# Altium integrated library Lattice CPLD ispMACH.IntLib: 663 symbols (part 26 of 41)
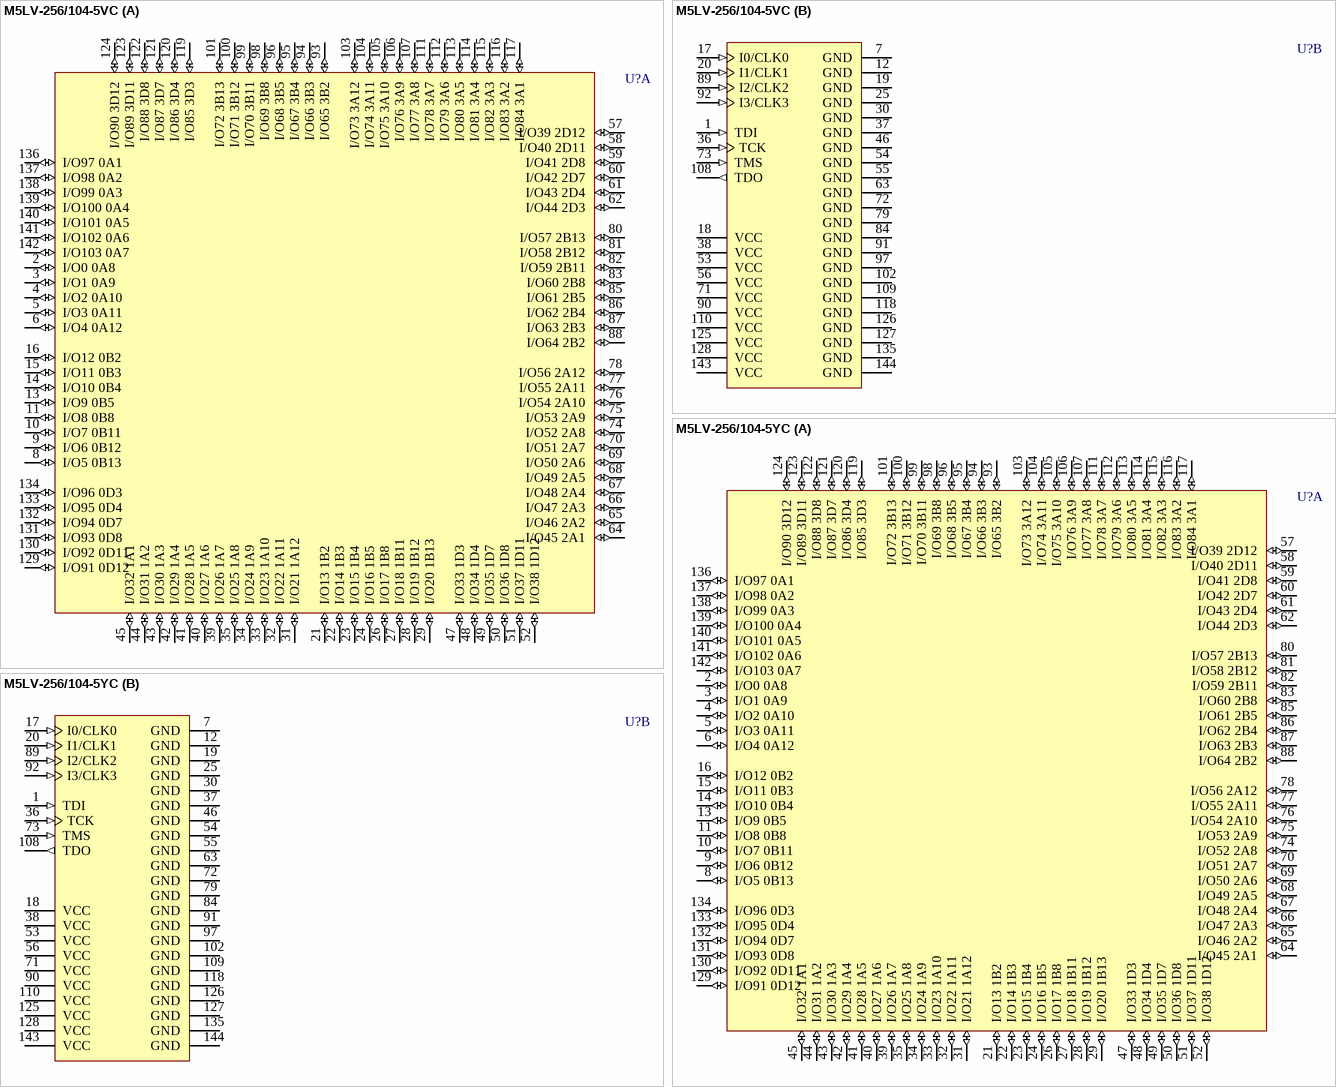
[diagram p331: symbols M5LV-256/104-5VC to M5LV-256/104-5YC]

## M5LV-256/104-5YC
designator U?
High-Density and High-I/O Complex PLD
footprint PQFP144_N (QFP, 144-Leads, Body 28 x 28mm, Pitch 0.65mm, IPC Medium Density)
footprint PQFP144_L (QFP, 144-Leads, Body 28 x 28mm, Pitch 0.65mm, IPC High Density)
footprint PQFP144_M (QFP, 144-Leads, Body 28 x 28mm, Pitch 0.65mm, IPC Low Density)
3D model M5LV-PQFP144 (144-Pin Quad Flat Pack 0.65 mm Pitch)
part A pins: 2 I/O0 0A8 (io), 3 I/O1 0A9 (io), 4 I/O2 0A10 (io), 5 I/O3 0A11 (io), 6 I/O4 0A12 (io), 8 I/O5 0B13 (io), 9 I/O6 0B12 (io), 10 I/O7 0B11 (io), 11 I/O8 0B8 (io), 13 I/O9 0B5 (io), 14 I/O10 0B4 (io), 15 I/O11 0B3 (io), 16 I/O12 0B2 (io), 21 I/O13 1B2 (io), 22 I/O14 1B3 (io), 23 I/O15 1B4 (io), 24 I/O16 1B5 (io), 26 I/O17 1B8 (io), 27 I/O18 1B11 (io), 28 I/O19 1B12 (io), 29 I/O20 1B13 (io), 31 I/O21 1A12 (io), 32 I/O22 1A11 (io), 33 I/O23 1A10 (io), 34 I/O24 1A9 (io), 35 I/O25 1A8 (io), 39 I/O26 1A7 (io), 40 I/O27 1A6 (io), 41 I/O28 1A5 (io), 42 I/O29 1A4 (io), 43 I/O30 1A3 (io), 44 I/O31 1A2 (io), 45 I/O32 1A1 (io), 47 I/O33 1D3 (io), 48 I/O34 1D4 (io), 49 I/O35 1D7 (io), 50 I/O36 1D8 (io), 51 I/O37 1D11 (io), 52 I/O38 1D12 (io), 57 I/O39 2D12 (io), 58 I/O40 2D11 (io), 59 I/O41 2D8 (io), 60 I/O42 2D7 (io), 61 I/O43 2D4 (io), 62 I/O44 2D3 (io), 64 I/O45 2A1 (io), 65 I/O46 2A2 (io), 66 I/O47 2A3 (io), 67 I/O48 2A4 (io), 68 I/O49 2A5 (io), 69 I/O50 2A6 (io), 70 I/O51 2A7 (io), 74 I/O52 2A8 (io), 75 I/O53 2A9 (io), 76 I/O54 2A10 (io), 77 I/O55 2A11 (io), 78 I/O56 2A12 (io), 80 I/O57 2B13 (io), 81 I/O58 2B12 (io), 82 I/O59 2B11 (io), 83 I/O60 2B8 (io), 85 I/O61 2B5 (io), 86 I/O62 2B4 (io), 87 I/O63 2B3 (io), 88 I/O64 2B2 (io), 93 I/O65 3B2 (io), 94 I/O66 3B3 (io), 95 I/O67 3B4 (io), 96 I/O68 3B5 (io), 98 I/O69 3B8 (io), 99 I/O70 3B11 (io), 100 I/O71 3B12 (io), 101 I/O72 3B13 (io), 103 I/O73 3A12 (io), 104 I/O74 3A11 (io), 105 I/O75 3A10 (io), 106 I/O76 3A9 (io), 107 I/O77 3A8 (io), 111 I/O78 3A7 (io), 112 I/O79 3A6 (io), 113 I/O80 3A5 (io), 114 I/O81 3A4 (io), 115 I/O82 3A3 (io), 116 I/O83 3A2 (io), 117 I/O84 3A1 (io), 119 I/O85 3D3 (io), 120 I/O86 3D4 (io), 121 I/O87 3D7 (io), 122 I/O88 3D8 (io), 123 I/O89 3D11 (io), 124 I/O90 3D12 (io), 129 I/O91 0D12 (io), 130 I/O92 0D11 (io), 131 I/O93 0D8 (io), 132 I/O94 0D7 (io), 133 I/O95 0D4 (io), 134 I/O96 0D3 (io), 136 I/O97 0A1 (io), 137 I/O98 0A2 (io), 138 I/O99 0A3 (io), 139 I/O100 0A4 (io), 140 I/O101 0A5 (io), 141 I/O102 0A6 (io), 142 I/O103 0A7 (io)
part B pins: 1 TDI (in), 7 GND (power), 12 GND (power), 17 I0/CLK0 (in), 18 VCC (power), 19 GND (power), 20 I1/CLK1 (in), 25 GND (power), 30 GND (power), 36 TCK (in), 37 GND (power), 38 VCC (power), 46 GND (power), 53 VCC (power), 54 GND (power), 55 GND (power), 56 VCC (power), 63 GND (power), 71 VCC (power), 72 GND (power), 73 TMS (in), 79 GND (power), 84 GND (power), 89 I2/CLK2 (in), 90 VCC (power), 91 GND (power), 92 I3/CLK3 (in), 97 GND (power), 102 GND (power), 108 TDO (out), 109 GND (power), 110 VCC (power), 118 GND (power), 125 VCC (power), 126 GND (power), 127 GND (power), 128 VCC (power), 135 GND (power), 143 VCC (power), 144 GND (power)

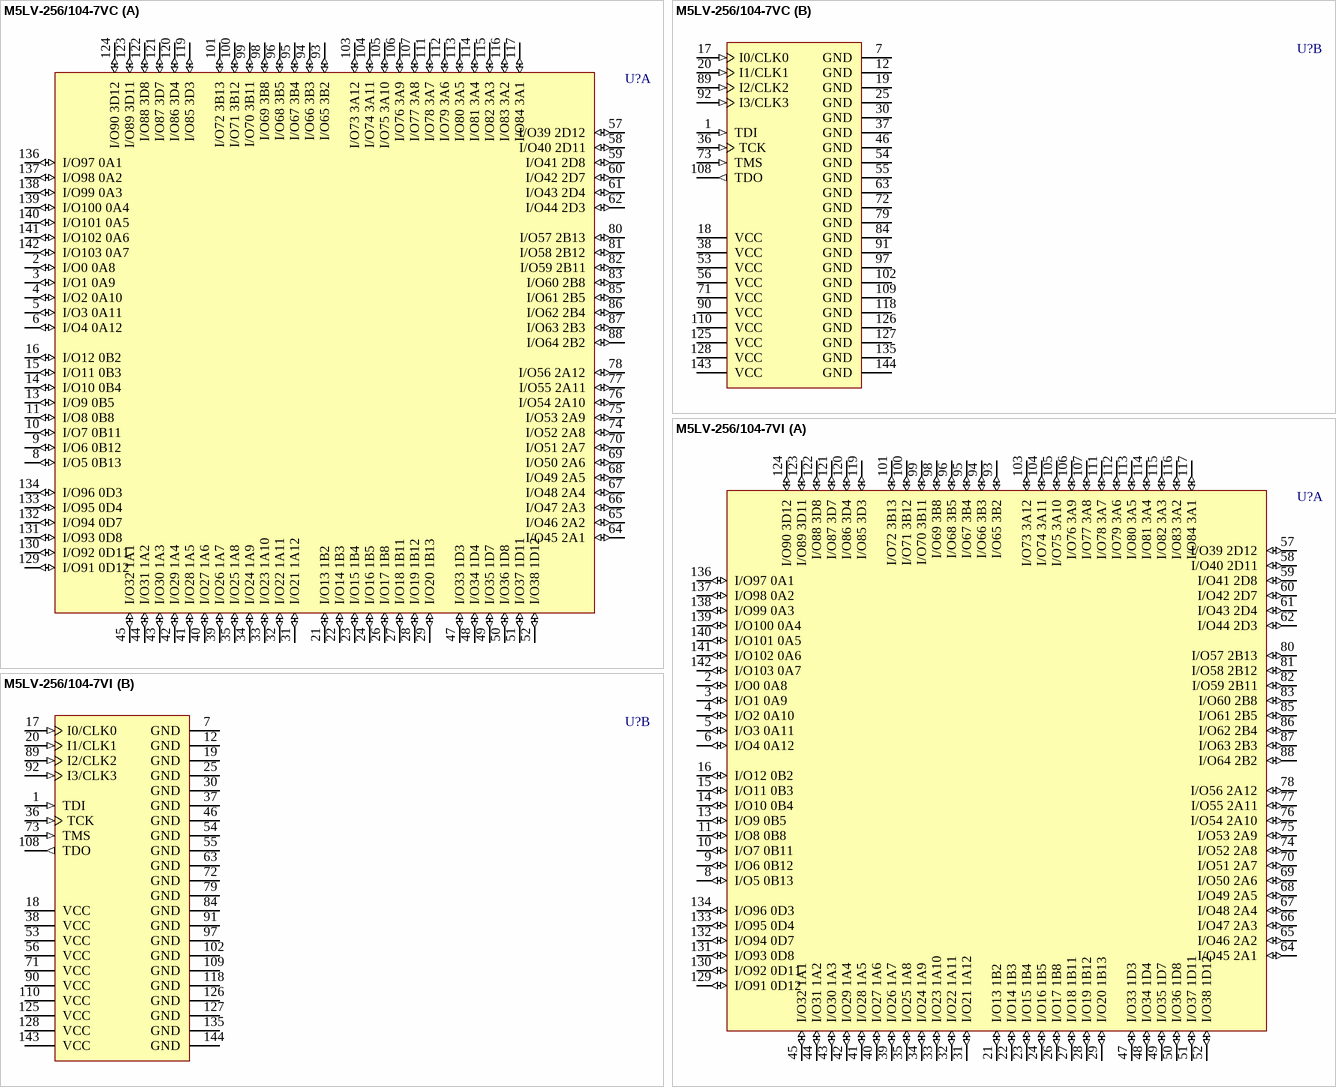
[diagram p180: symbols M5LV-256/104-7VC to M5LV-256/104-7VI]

## M5LV-256/104-7VC
designator U?
High-Density and High-I/O Complex PLD
footprint TQFP144_N (Thin QFP, 144-Leads, Body 20x20mm, Pitch 0.5mm, IPC Medium Density)
footprint TQFP144_L (Thin QFP, 144-Leads, Body 20x20mm, Pitch 0.5mm, IPC High Density)
footprint TQFP144_M (Thin QFP, 144-Leads, Body 20x20mm, Pitch 0.5mm, IPC Low Density)
3D model M5LV-TQFP144 (144-Pin Thin Quad Flat Pack (TQFP144))
part A pins: 2 I/O0 0A8 (io), 3 I/O1 0A9 (io), 4 I/O2 0A10 (io), 5 I/O3 0A11 (io), 6 I/O4 0A12 (io), 8 I/O5 0B13 (io), 9 I/O6 0B12 (io), 10 I/O7 0B11 (io), 11 I/O8 0B8 (io), 13 I/O9 0B5 (io), 14 I/O10 0B4 (io), 15 I/O11 0B3 (io), 16 I/O12 0B2 (io), 21 I/O13 1B2 (io), 22 I/O14 1B3 (io), 23 I/O15 1B4 (io), 24 I/O16 1B5 (io), 26 I/O17 1B8 (io), 27 I/O18 1B11 (io), 28 I/O19 1B12 (io), 29 I/O20 1B13 (io), 31 I/O21 1A12 (io), 32 I/O22 1A11 (io), 33 I/O23 1A10 (io), 34 I/O24 1A9 (io), 35 I/O25 1A8 (io), 39 I/O26 1A7 (io), 40 I/O27 1A6 (io), 41 I/O28 1A5 (io), 42 I/O29 1A4 (io), 43 I/O30 1A3 (io), 44 I/O31 1A2 (io), 45 I/O32 1A1 (io), 47 I/O33 1D3 (io), 48 I/O34 1D4 (io), 49 I/O35 1D7 (io), 50 I/O36 1D8 (io), 51 I/O37 1D11 (io), 52 I/O38 1D12 (io), 57 I/O39 2D12 (io), 58 I/O40 2D11 (io), 59 I/O41 2D8 (io), 60 I/O42 2D7 (io), 61 I/O43 2D4 (io), 62 I/O44 2D3 (io), 64 I/O45 2A1 (io), 65 I/O46 2A2 (io), 66 I/O47 2A3 (io), 67 I/O48 2A4 (io), 68 I/O49 2A5 (io), 69 I/O50 2A6 (io), 70 I/O51 2A7 (io), 74 I/O52 2A8 (io), 75 I/O53 2A9 (io), 76 I/O54 2A10 (io), 77 I/O55 2A11 (io), 78 I/O56 2A12 (io), 80 I/O57 2B13 (io), 81 I/O58 2B12 (io), 82 I/O59 2B11 (io), 83 I/O60 2B8 (io), 85 I/O61 2B5 (io), 86 I/O62 2B4 (io), 87 I/O63 2B3 (io), 88 I/O64 2B2 (io), 93 I/O65 3B2 (io), 94 I/O66 3B3 (io), 95 I/O67 3B4 (io), 96 I/O68 3B5 (io), 98 I/O69 3B8 (io), 99 I/O70 3B11 (io), 100 I/O71 3B12 (io), 101 I/O72 3B13 (io), 103 I/O73 3A12 (io), 104 I/O74 3A11 (io), 105 I/O75 3A10 (io), 106 I/O76 3A9 (io), 107 I/O77 3A8 (io), 111 I/O78 3A7 (io), 112 I/O79 3A6 (io), 113 I/O80 3A5 (io), 114 I/O81 3A4 (io), 115 I/O82 3A3 (io), 116 I/O83 3A2 (io), 117 I/O84 3A1 (io), 119 I/O85 3D3 (io), 120 I/O86 3D4 (io), 121 I/O87 3D7 (io), 122 I/O88 3D8 (io), 123 I/O89 3D11 (io), 124 I/O90 3D12 (io), 129 I/O91 0D12 (io), 130 I/O92 0D11 (io), 131 I/O93 0D8 (io), 132 I/O94 0D7 (io), 133 I/O95 0D4 (io), 134 I/O96 0D3 (io), 136 I/O97 0A1 (io), 137 I/O98 0A2 (io), 138 I/O99 0A3 (io), 139 I/O100 0A4 (io), 140 I/O101 0A5 (io), 141 I/O102 0A6 (io), 142 I/O103 0A7 (io)
part B pins: 1 TDI (in), 7 GND (power), 12 GND (power), 17 I0/CLK0 (in), 18 VCC (power), 19 GND (power), 20 I1/CLK1 (in), 25 GND (power), 30 GND (power), 36 TCK (in), 37 GND (power), 38 VCC (power), 46 GND (power), 53 VCC (power), 54 GND (power), 55 GND (power), 56 VCC (power), 63 GND (power), 71 VCC (power), 72 GND (power), 73 TMS (in), 79 GND (power), 84 GND (power), 89 I2/CLK2 (in), 90 VCC (power), 91 GND (power), 92 I3/CLK3 (in), 97 GND (power), 102 GND (power), 108 TDO (out), 109 GND (power), 110 VCC (power), 118 GND (power), 125 VCC (power), 126 GND (power), 127 GND (power), 128 VCC (power), 135 GND (power), 143 VCC (power), 144 GND (power)

## M5LV-256/104-7VI
designator U?
High-Density and High-I/O Complex PLD
footprint TQFP144_N (Thin QFP, 144-Leads, Body 20x20mm, Pitch 0.5mm, IPC Medium Density)
footprint TQFP144_L (Thin QFP, 144-Leads, Body 20x20mm, Pitch 0.5mm, IPC High Density)
footprint TQFP144_M (Thin QFP, 144-Leads, Body 20x20mm, Pitch 0.5mm, IPC Low Density)
3D model M5LV-TQFP144 (144-Pin Thin Quad Flat Pack (TQFP144))
part A pins: 2 I/O0 0A8 (io), 3 I/O1 0A9 (io), 4 I/O2 0A10 (io), 5 I/O3 0A11 (io), 6 I/O4 0A12 (io), 8 I/O5 0B13 (io), 9 I/O6 0B12 (io), 10 I/O7 0B11 (io), 11 I/O8 0B8 (io), 13 I/O9 0B5 (io), 14 I/O10 0B4 (io), 15 I/O11 0B3 (io), 16 I/O12 0B2 (io), 21 I/O13 1B2 (io), 22 I/O14 1B3 (io), 23 I/O15 1B4 (io), 24 I/O16 1B5 (io), 26 I/O17 1B8 (io), 27 I/O18 1B11 (io), 28 I/O19 1B12 (io), 29 I/O20 1B13 (io), 31 I/O21 1A12 (io), 32 I/O22 1A11 (io), 33 I/O23 1A10 (io), 34 I/O24 1A9 (io), 35 I/O25 1A8 (io), 39 I/O26 1A7 (io), 40 I/O27 1A6 (io), 41 I/O28 1A5 (io), 42 I/O29 1A4 (io), 43 I/O30 1A3 (io), 44 I/O31 1A2 (io), 45 I/O32 1A1 (io), 47 I/O33 1D3 (io), 48 I/O34 1D4 (io), 49 I/O35 1D7 (io), 50 I/O36 1D8 (io), 51 I/O37 1D11 (io), 52 I/O38 1D12 (io), 57 I/O39 2D12 (io), 58 I/O40 2D11 (io), 59 I/O41 2D8 (io), 60 I/O42 2D7 (io), 61 I/O43 2D4 (io), 62 I/O44 2D3 (io), 64 I/O45 2A1 (io), 65 I/O46 2A2 (io), 66 I/O47 2A3 (io), 67 I/O48 2A4 (io), 68 I/O49 2A5 (io), 69 I/O50 2A6 (io), 70 I/O51 2A7 (io), 74 I/O52 2A8 (io), 75 I/O53 2A9 (io), 76 I/O54 2A10 (io), 77 I/O55 2A11 (io), 78 I/O56 2A12 (io), 80 I/O57 2B13 (io), 81 I/O58 2B12 (io), 82 I/O59 2B11 (io), 83 I/O60 2B8 (io), 85 I/O61 2B5 (io), 86 I/O62 2B4 (io), 87 I/O63 2B3 (io), 88 I/O64 2B2 (io), 93 I/O65 3B2 (io), 94 I/O66 3B3 (io), 95 I/O67 3B4 (io), 96 I/O68 3B5 (io), 98 I/O69 3B8 (io), 99 I/O70 3B11 (io), 100 I/O71 3B12 (io), 101 I/O72 3B13 (io), 103 I/O73 3A12 (io), 104 I/O74 3A11 (io), 105 I/O75 3A10 (io), 106 I/O76 3A9 (io), 107 I/O77 3A8 (io), 111 I/O78 3A7 (io), 112 I/O79 3A6 (io), 113 I/O80 3A5 (io), 114 I/O81 3A4 (io), 115 I/O82 3A3 (io), 116 I/O83 3A2 (io), 117 I/O84 3A1 (io), 119 I/O85 3D3 (io), 120 I/O86 3D4 (io), 121 I/O87 3D7 (io), 122 I/O88 3D8 (io), 123 I/O89 3D11 (io), 124 I/O90 3D12 (io), 129 I/O91 0D12 (io), 130 I/O92 0D11 (io), 131 I/O93 0D8 (io), 132 I/O94 0D7 (io), 133 I/O95 0D4 (io), 134 I/O96 0D3 (io), 136 I/O97 0A1 (io), 137 I/O98 0A2 (io), 138 I/O99 0A3 (io), 139 I/O100 0A4 (io), 140 I/O101 0A5 (io), 141 I/O102 0A6 (io), 142 I/O103 0A7 (io)
part B pins: 1 TDI (in), 7 GND (power), 12 GND (power), 17 I0/CLK0 (in), 18 VCC (power), 19 GND (power), 20 I1/CLK1 (in), 25 GND (power), 30 GND (power), 36 TCK (in), 37 GND (power), 38 VCC (power), 46 GND (power), 53 VCC (power), 54 GND (power), 55 GND (power), 56 VCC (power), 63 GND (power), 71 VCC (power), 72 GND (power), 73 TMS (in), 79 GND (power), 84 GND (power), 89 I2/CLK2 (in), 90 VCC (power), 91 GND (power), 92 I3/CLK3 (in), 97 GND (power), 102 GND (power), 108 TDO (out), 109 GND (power), 110 VCC (power), 118 GND (power), 125 VCC (power), 126 GND (power), 127 GND (power), 128 VCC (power), 135 GND (power), 143 VCC (power), 144 GND (power)

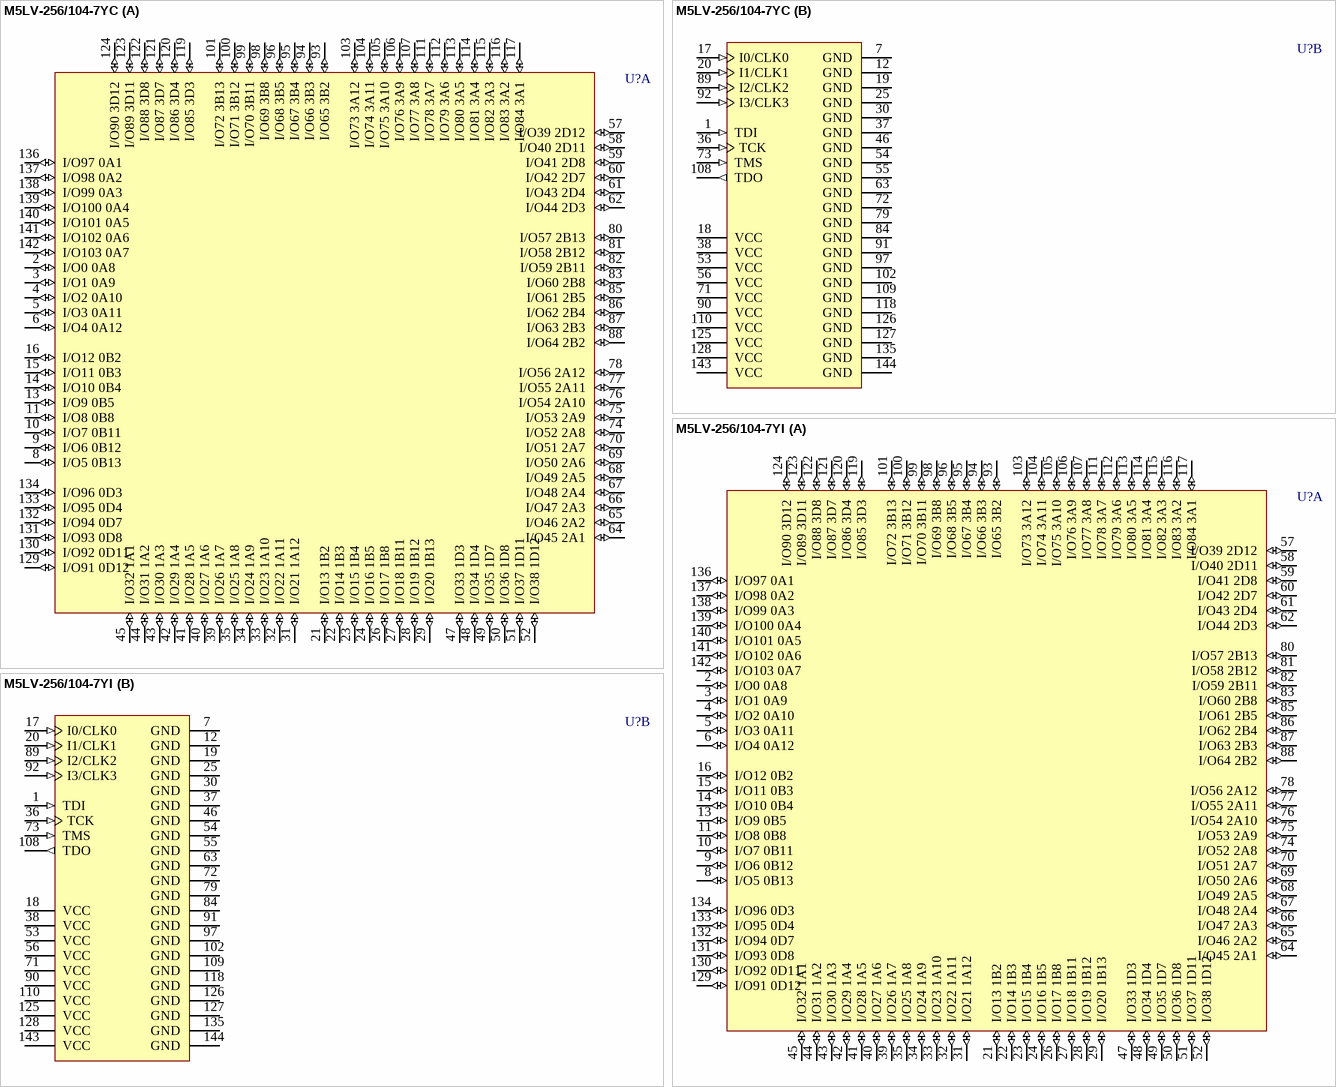
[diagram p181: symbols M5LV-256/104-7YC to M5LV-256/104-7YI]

## M5LV-256/104-7YC
designator U?
High-Density and High-I/O Complex PLD
footprint PQFP144_N (QFP, 144-Leads, Body 28 x 28mm, Pitch 0.65mm, IPC Medium Density)
footprint PQFP144_L (QFP, 144-Leads, Body 28 x 28mm, Pitch 0.65mm, IPC High Density)
footprint PQFP144_M (QFP, 144-Leads, Body 28 x 28mm, Pitch 0.65mm, IPC Low Density)
3D model M5LV-PQFP144 (144-Pin Quad Flat Pack 0.65 mm Pitch)
part A pins: 2 I/O0 0A8 (io), 3 I/O1 0A9 (io), 4 I/O2 0A10 (io), 5 I/O3 0A11 (io), 6 I/O4 0A12 (io), 8 I/O5 0B13 (io), 9 I/O6 0B12 (io), 10 I/O7 0B11 (io), 11 I/O8 0B8 (io), 13 I/O9 0B5 (io), 14 I/O10 0B4 (io), 15 I/O11 0B3 (io), 16 I/O12 0B2 (io), 21 I/O13 1B2 (io), 22 I/O14 1B3 (io), 23 I/O15 1B4 (io), 24 I/O16 1B5 (io), 26 I/O17 1B8 (io), 27 I/O18 1B11 (io), 28 I/O19 1B12 (io), 29 I/O20 1B13 (io), 31 I/O21 1A12 (io), 32 I/O22 1A11 (io), 33 I/O23 1A10 (io), 34 I/O24 1A9 (io), 35 I/O25 1A8 (io), 39 I/O26 1A7 (io), 40 I/O27 1A6 (io), 41 I/O28 1A5 (io), 42 I/O29 1A4 (io), 43 I/O30 1A3 (io), 44 I/O31 1A2 (io), 45 I/O32 1A1 (io), 47 I/O33 1D3 (io), 48 I/O34 1D4 (io), 49 I/O35 1D7 (io), 50 I/O36 1D8 (io), 51 I/O37 1D11 (io), 52 I/O38 1D12 (io), 57 I/O39 2D12 (io), 58 I/O40 2D11 (io), 59 I/O41 2D8 (io), 60 I/O42 2D7 (io), 61 I/O43 2D4 (io), 62 I/O44 2D3 (io), 64 I/O45 2A1 (io), 65 I/O46 2A2 (io), 66 I/O47 2A3 (io), 67 I/O48 2A4 (io), 68 I/O49 2A5 (io), 69 I/O50 2A6 (io), 70 I/O51 2A7 (io), 74 I/O52 2A8 (io), 75 I/O53 2A9 (io), 76 I/O54 2A10 (io), 77 I/O55 2A11 (io), 78 I/O56 2A12 (io), 80 I/O57 2B13 (io), 81 I/O58 2B12 (io), 82 I/O59 2B11 (io), 83 I/O60 2B8 (io), 85 I/O61 2B5 (io), 86 I/O62 2B4 (io), 87 I/O63 2B3 (io), 88 I/O64 2B2 (io), 93 I/O65 3B2 (io), 94 I/O66 3B3 (io), 95 I/O67 3B4 (io), 96 I/O68 3B5 (io), 98 I/O69 3B8 (io), 99 I/O70 3B11 (io), 100 I/O71 3B12 (io), 101 I/O72 3B13 (io), 103 I/O73 3A12 (io), 104 I/O74 3A11 (io), 105 I/O75 3A10 (io), 106 I/O76 3A9 (io), 107 I/O77 3A8 (io), 111 I/O78 3A7 (io), 112 I/O79 3A6 (io), 113 I/O80 3A5 (io), 114 I/O81 3A4 (io), 115 I/O82 3A3 (io), 116 I/O83 3A2 (io), 117 I/O84 3A1 (io), 119 I/O85 3D3 (io), 120 I/O86 3D4 (io), 121 I/O87 3D7 (io), 122 I/O88 3D8 (io), 123 I/O89 3D11 (io), 124 I/O90 3D12 (io), 129 I/O91 0D12 (io), 130 I/O92 0D11 (io), 131 I/O93 0D8 (io), 132 I/O94 0D7 (io), 133 I/O95 0D4 (io), 134 I/O96 0D3 (io), 136 I/O97 0A1 (io), 137 I/O98 0A2 (io), 138 I/O99 0A3 (io), 139 I/O100 0A4 (io), 140 I/O101 0A5 (io), 141 I/O102 0A6 (io), 142 I/O103 0A7 (io)
part B pins: 1 TDI (in), 7 GND (power), 12 GND (power), 17 I0/CLK0 (in), 18 VCC (power), 19 GND (power), 20 I1/CLK1 (in), 25 GND (power), 30 GND (power), 36 TCK (in), 37 GND (power), 38 VCC (power), 46 GND (power), 53 VCC (power), 54 GND (power), 55 GND (power), 56 VCC (power), 63 GND (power), 71 VCC (power), 72 GND (power), 73 TMS (in), 79 GND (power), 84 GND (power), 89 I2/CLK2 (in), 90 VCC (power), 91 GND (power), 92 I3/CLK3 (in), 97 GND (power), 102 GND (power), 108 TDO (out), 109 GND (power), 110 VCC (power), 118 GND (power), 125 VCC (power), 126 GND (power), 127 GND (power), 128 VCC (power), 135 GND (power), 143 VCC (power), 144 GND (power)

## M5LV-256/104-7YI
designator U?
High-Density and High-I/O Complex PLD
footprint PQFP144_N (QFP, 144-Leads, Body 28 x 28mm, Pitch 0.65mm, IPC Medium Density)
footprint PQFP144_L (QFP, 144-Leads, Body 28 x 28mm, Pitch 0.65mm, IPC High Density)
footprint PQFP144_M (QFP, 144-Leads, Body 28 x 28mm, Pitch 0.65mm, IPC Low Density)
3D model M5LV-PQFP144 (144-Pin Quad Flat Pack 0.65 mm Pitch)
part A pins: 2 I/O0 0A8 (io), 3 I/O1 0A9 (io), 4 I/O2 0A10 (io), 5 I/O3 0A11 (io), 6 I/O4 0A12 (io), 8 I/O5 0B13 (io), 9 I/O6 0B12 (io), 10 I/O7 0B11 (io), 11 I/O8 0B8 (io), 13 I/O9 0B5 (io), 14 I/O10 0B4 (io), 15 I/O11 0B3 (io), 16 I/O12 0B2 (io), 21 I/O13 1B2 (io), 22 I/O14 1B3 (io), 23 I/O15 1B4 (io), 24 I/O16 1B5 (io), 26 I/O17 1B8 (io), 27 I/O18 1B11 (io), 28 I/O19 1B12 (io), 29 I/O20 1B13 (io), 31 I/O21 1A12 (io), 32 I/O22 1A11 (io), 33 I/O23 1A10 (io), 34 I/O24 1A9 (io), 35 I/O25 1A8 (io), 39 I/O26 1A7 (io), 40 I/O27 1A6 (io), 41 I/O28 1A5 (io), 42 I/O29 1A4 (io), 43 I/O30 1A3 (io), 44 I/O31 1A2 (io), 45 I/O32 1A1 (io), 47 I/O33 1D3 (io), 48 I/O34 1D4 (io), 49 I/O35 1D7 (io), 50 I/O36 1D8 (io), 51 I/O37 1D11 (io), 52 I/O38 1D12 (io), 57 I/O39 2D12 (io), 58 I/O40 2D11 (io), 59 I/O41 2D8 (io), 60 I/O42 2D7 (io), 61 I/O43 2D4 (io), 62 I/O44 2D3 (io), 64 I/O45 2A1 (io), 65 I/O46 2A2 (io), 66 I/O47 2A3 (io), 67 I/O48 2A4 (io), 68 I/O49 2A5 (io), 69 I/O50 2A6 (io), 70 I/O51 2A7 (io), 74 I/O52 2A8 (io), 75 I/O53 2A9 (io), 76 I/O54 2A10 (io), 77 I/O55 2A11 (io), 78 I/O56 2A12 (io), 80 I/O57 2B13 (io), 81 I/O58 2B12 (io), 82 I/O59 2B11 (io), 83 I/O60 2B8 (io), 85 I/O61 2B5 (io), 86 I/O62 2B4 (io), 87 I/O63 2B3 (io), 88 I/O64 2B2 (io), 93 I/O65 3B2 (io), 94 I/O66 3B3 (io), 95 I/O67 3B4 (io), 96 I/O68 3B5 (io), 98 I/O69 3B8 (io), 99 I/O70 3B11 (io), 100 I/O71 3B12 (io), 101 I/O72 3B13 (io), 103 I/O73 3A12 (io), 104 I/O74 3A11 (io), 105 I/O75 3A10 (io), 106 I/O76 3A9 (io), 107 I/O77 3A8 (io), 111 I/O78 3A7 (io), 112 I/O79 3A6 (io), 113 I/O80 3A5 (io), 114 I/O81 3A4 (io), 115 I/O82 3A3 (io), 116 I/O83 3A2 (io), 117 I/O84 3A1 (io), 119 I/O85 3D3 (io), 120 I/O86 3D4 (io), 121 I/O87 3D7 (io), 122 I/O88 3D8 (io), 123 I/O89 3D11 (io), 124 I/O90 3D12 (io), 129 I/O91 0D12 (io), 130 I/O92 0D11 (io), 131 I/O93 0D8 (io), 132 I/O94 0D7 (io), 133 I/O95 0D4 (io), 134 I/O96 0D3 (io), 136 I/O97 0A1 (io), 137 I/O98 0A2 (io), 138 I/O99 0A3 (io), 139 I/O100 0A4 (io), 140 I/O101 0A5 (io), 141 I/O102 0A6 (io), 142 I/O103 0A7 (io)
part B pins: 1 TDI (in), 7 GND (power), 12 GND (power), 17 I0/CLK0 (in), 18 VCC (power), 19 GND (power), 20 I1/CLK1 (in), 25 GND (power), 30 GND (power), 36 TCK (in), 37 GND (power), 38 VCC (power), 46 GND (power), 53 VCC (power), 54 GND (power), 55 GND (power), 56 VCC (power), 63 GND (power), 71 VCC (power), 72 GND (power), 73 TMS (in), 79 GND (power), 84 GND (power), 89 I2/CLK2 (in), 90 VCC (power), 91 GND (power), 92 I3/CLK3 (in), 97 GND (power), 102 GND (power), 108 TDO (out), 109 GND (power), 110 VCC (power), 118 GND (power), 125 VCC (power), 126 GND (power), 127 GND (power), 128 VCC (power), 135 GND (power), 143 VCC (power), 144 GND (power)

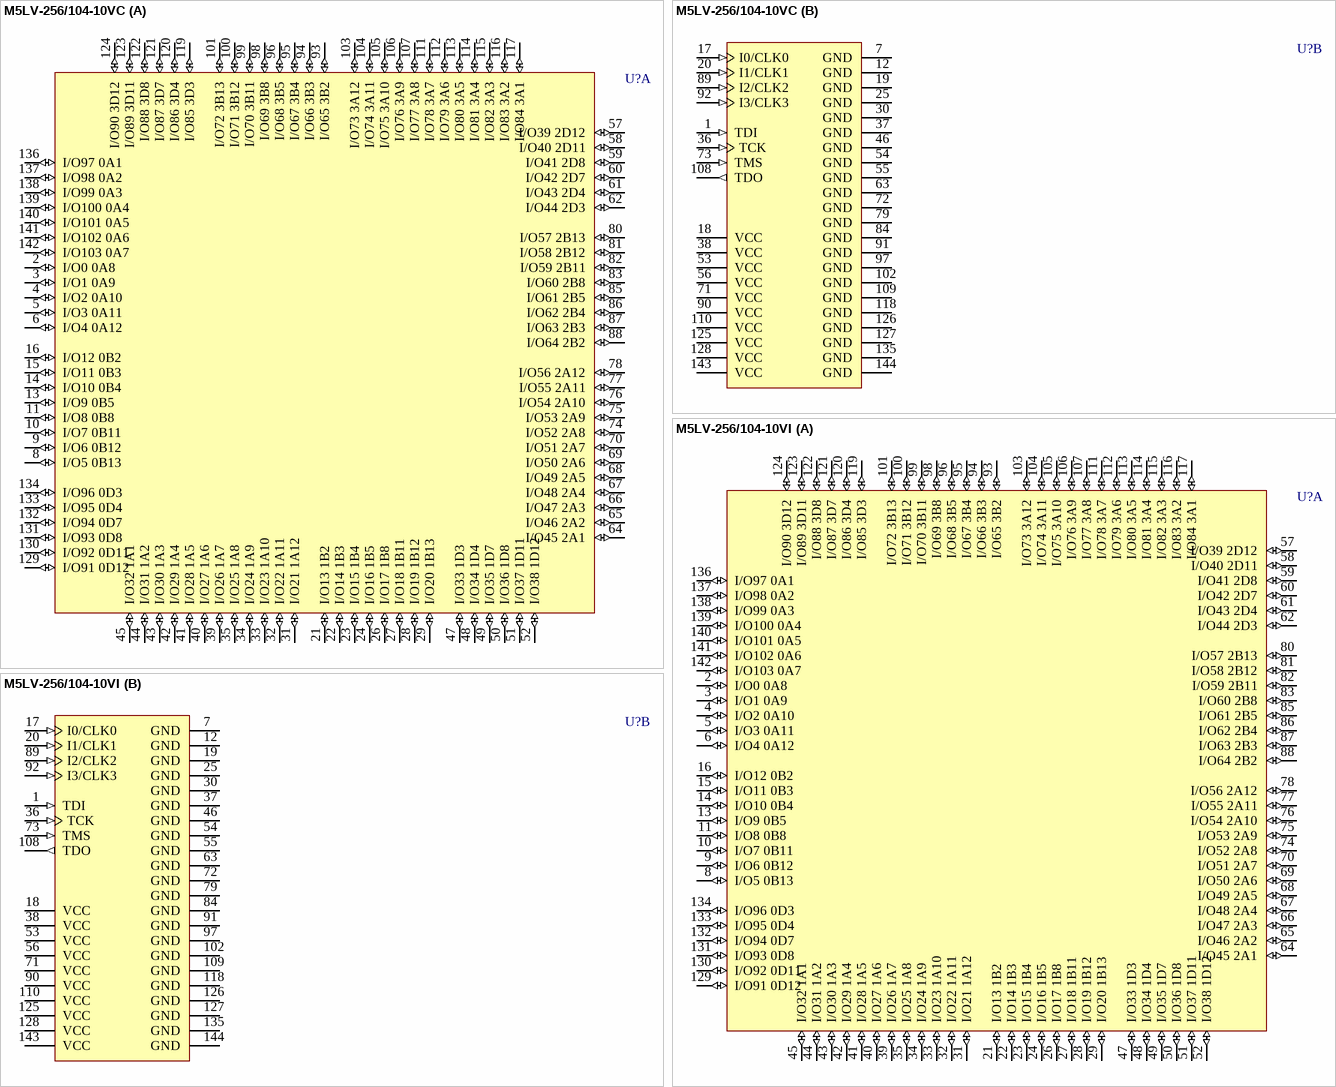
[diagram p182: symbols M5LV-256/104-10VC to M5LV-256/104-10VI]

## M5LV-256/104-10VC
designator U?
High-Density and High-I/O Complex PLD
footprint TQFP144_N (Thin QFP, 144-Leads, Body 20x20mm, Pitch 0.5mm, IPC Medium Density)
footprint TQFP144_L (Thin QFP, 144-Leads, Body 20x20mm, Pitch 0.5mm, IPC High Density)
footprint TQFP144_M (Thin QFP, 144-Leads, Body 20x20mm, Pitch 0.5mm, IPC Low Density)
3D model M5LV-TQFP144 (144-Pin Thin Quad Flat Pack (TQFP144))
part A pins: 2 I/O0 0A8 (io), 3 I/O1 0A9 (io), 4 I/O2 0A10 (io), 5 I/O3 0A11 (io), 6 I/O4 0A12 (io), 8 I/O5 0B13 (io), 9 I/O6 0B12 (io), 10 I/O7 0B11 (io), 11 I/O8 0B8 (io), 13 I/O9 0B5 (io), 14 I/O10 0B4 (io), 15 I/O11 0B3 (io), 16 I/O12 0B2 (io), 21 I/O13 1B2 (io), 22 I/O14 1B3 (io), 23 I/O15 1B4 (io), 24 I/O16 1B5 (io), 26 I/O17 1B8 (io), 27 I/O18 1B11 (io), 28 I/O19 1B12 (io), 29 I/O20 1B13 (io), 31 I/O21 1A12 (io), 32 I/O22 1A11 (io), 33 I/O23 1A10 (io), 34 I/O24 1A9 (io), 35 I/O25 1A8 (io), 39 I/O26 1A7 (io), 40 I/O27 1A6 (io), 41 I/O28 1A5 (io), 42 I/O29 1A4 (io), 43 I/O30 1A3 (io), 44 I/O31 1A2 (io), 45 I/O32 1A1 (io), 47 I/O33 1D3 (io), 48 I/O34 1D4 (io), 49 I/O35 1D7 (io), 50 I/O36 1D8 (io), 51 I/O37 1D11 (io), 52 I/O38 1D12 (io), 57 I/O39 2D12 (io), 58 I/O40 2D11 (io), 59 I/O41 2D8 (io), 60 I/O42 2D7 (io), 61 I/O43 2D4 (io), 62 I/O44 2D3 (io), 64 I/O45 2A1 (io), 65 I/O46 2A2 (io), 66 I/O47 2A3 (io), 67 I/O48 2A4 (io), 68 I/O49 2A5 (io), 69 I/O50 2A6 (io), 70 I/O51 2A7 (io), 74 I/O52 2A8 (io), 75 I/O53 2A9 (io), 76 I/O54 2A10 (io), 77 I/O55 2A11 (io), 78 I/O56 2A12 (io), 80 I/O57 2B13 (io), 81 I/O58 2B12 (io), 82 I/O59 2B11 (io), 83 I/O60 2B8 (io), 85 I/O61 2B5 (io), 86 I/O62 2B4 (io), 87 I/O63 2B3 (io), 88 I/O64 2B2 (io), 93 I/O65 3B2 (io), 94 I/O66 3B3 (io), 95 I/O67 3B4 (io), 96 I/O68 3B5 (io), 98 I/O69 3B8 (io), 99 I/O70 3B11 (io), 100 I/O71 3B12 (io), 101 I/O72 3B13 (io), 103 I/O73 3A12 (io), 104 I/O74 3A11 (io), 105 I/O75 3A10 (io), 106 I/O76 3A9 (io), 107 I/O77 3A8 (io), 111 I/O78 3A7 (io), 112 I/O79 3A6 (io), 113 I/O80 3A5 (io), 114 I/O81 3A4 (io), 115 I/O82 3A3 (io), 116 I/O83 3A2 (io), 117 I/O84 3A1 (io), 119 I/O85 3D3 (io), 120 I/O86 3D4 (io), 121 I/O87 3D7 (io), 122 I/O88 3D8 (io), 123 I/O89 3D11 (io), 124 I/O90 3D12 (io), 129 I/O91 0D12 (io), 130 I/O92 0D11 (io), 131 I/O93 0D8 (io), 132 I/O94 0D7 (io), 133 I/O95 0D4 (io), 134 I/O96 0D3 (io), 136 I/O97 0A1 (io), 137 I/O98 0A2 (io), 138 I/O99 0A3 (io), 139 I/O100 0A4 (io), 140 I/O101 0A5 (io), 141 I/O102 0A6 (io), 142 I/O103 0A7 (io)
part B pins: 1 TDI (in), 7 GND (power), 12 GND (power), 17 I0/CLK0 (in), 18 VCC (power), 19 GND (power), 20 I1/CLK1 (in), 25 GND (power), 30 GND (power), 36 TCK (in), 37 GND (power), 38 VCC (power), 46 GND (power), 53 VCC (power), 54 GND (power), 55 GND (power), 56 VCC (power), 63 GND (power), 71 VCC (power), 72 GND (power), 73 TMS (in), 79 GND (power), 84 GND (power), 89 I2/CLK2 (in), 90 VCC (power), 91 GND (power), 92 I3/CLK3 (in), 97 GND (power), 102 GND (power), 108 TDO (out), 109 GND (power), 110 VCC (power), 118 GND (power), 125 VCC (power), 126 GND (power), 127 GND (power), 128 VCC (power), 135 GND (power), 143 VCC (power), 144 GND (power)

## M5LV-256/104-10VI
designator U?
High-Density and High-I/O Complex PLD
footprint TQFP144_N (Thin QFP, 144-Leads, Body 20x20mm, Pitch 0.5mm, IPC Medium Density)
footprint TQFP144_L (Thin QFP, 144-Leads, Body 20x20mm, Pitch 0.5mm, IPC High Density)
footprint TQFP144_M (Thin QFP, 144-Leads, Body 20x20mm, Pitch 0.5mm, IPC Low Density)
3D model M5LV-TQFP144 (144-Pin Thin Quad Flat Pack (TQFP144))
part A pins: 2 I/O0 0A8 (io), 3 I/O1 0A9 (io), 4 I/O2 0A10 (io), 5 I/O3 0A11 (io), 6 I/O4 0A12 (io), 8 I/O5 0B13 (io), 9 I/O6 0B12 (io), 10 I/O7 0B11 (io), 11 I/O8 0B8 (io), 13 I/O9 0B5 (io), 14 I/O10 0B4 (io), 15 I/O11 0B3 (io), 16 I/O12 0B2 (io), 21 I/O13 1B2 (io), 22 I/O14 1B3 (io), 23 I/O15 1B4 (io), 24 I/O16 1B5 (io), 26 I/O17 1B8 (io), 27 I/O18 1B11 (io), 28 I/O19 1B12 (io), 29 I/O20 1B13 (io), 31 I/O21 1A12 (io), 32 I/O22 1A11 (io), 33 I/O23 1A10 (io), 34 I/O24 1A9 (io), 35 I/O25 1A8 (io), 39 I/O26 1A7 (io), 40 I/O27 1A6 (io), 41 I/O28 1A5 (io), 42 I/O29 1A4 (io), 43 I/O30 1A3 (io), 44 I/O31 1A2 (io), 45 I/O32 1A1 (io), 47 I/O33 1D3 (io), 48 I/O34 1D4 (io), 49 I/O35 1D7 (io), 50 I/O36 1D8 (io), 51 I/O37 1D11 (io), 52 I/O38 1D12 (io), 57 I/O39 2D12 (io), 58 I/O40 2D11 (io), 59 I/O41 2D8 (io), 60 I/O42 2D7 (io), 61 I/O43 2D4 (io), 62 I/O44 2D3 (io), 64 I/O45 2A1 (io), 65 I/O46 2A2 (io), 66 I/O47 2A3 (io), 67 I/O48 2A4 (io), 68 I/O49 2A5 (io), 69 I/O50 2A6 (io), 70 I/O51 2A7 (io), 74 I/O52 2A8 (io), 75 I/O53 2A9 (io), 76 I/O54 2A10 (io), 77 I/O55 2A11 (io), 78 I/O56 2A12 (io), 80 I/O57 2B13 (io), 81 I/O58 2B12 (io), 82 I/O59 2B11 (io), 83 I/O60 2B8 (io), 85 I/O61 2B5 (io), 86 I/O62 2B4 (io), 87 I/O63 2B3 (io), 88 I/O64 2B2 (io), 93 I/O65 3B2 (io), 94 I/O66 3B3 (io), 95 I/O67 3B4 (io), 96 I/O68 3B5 (io), 98 I/O69 3B8 (io), 99 I/O70 3B11 (io), 100 I/O71 3B12 (io), 101 I/O72 3B13 (io), 103 I/O73 3A12 (io), 104 I/O74 3A11 (io), 105 I/O75 3A10 (io), 106 I/O76 3A9 (io), 107 I/O77 3A8 (io), 111 I/O78 3A7 (io), 112 I/O79 3A6 (io), 113 I/O80 3A5 (io), 114 I/O81 3A4 (io), 115 I/O82 3A3 (io), 116 I/O83 3A2 (io), 117 I/O84 3A1 (io), 119 I/O85 3D3 (io), 120 I/O86 3D4 (io), 121 I/O87 3D7 (io), 122 I/O88 3D8 (io), 123 I/O89 3D11 (io), 124 I/O90 3D12 (io), 129 I/O91 0D12 (io), 130 I/O92 0D11 (io), 131 I/O93 0D8 (io), 132 I/O94 0D7 (io), 133 I/O95 0D4 (io), 134 I/O96 0D3 (io), 136 I/O97 0A1 (io), 137 I/O98 0A2 (io), 138 I/O99 0A3 (io), 139 I/O100 0A4 (io), 140 I/O101 0A5 (io), 141 I/O102 0A6 (io), 142 I/O103 0A7 (io)
part B pins: 1 TDI (in), 7 GND (power), 12 GND (power), 17 I0/CLK0 (in), 18 VCC (power), 19 GND (power), 20 I1/CLK1 (in), 25 GND (power), 30 GND (power), 36 TCK (in), 37 GND (power), 38 VCC (power), 46 GND (power), 53 VCC (power), 54 GND (power), 55 GND (power), 56 VCC (power), 63 GND (power), 71 VCC (power), 72 GND (power), 73 TMS (in), 79 GND (power), 84 GND (power), 89 I2/CLK2 (in), 90 VCC (power), 91 GND (power), 92 I3/CLK3 (in), 97 GND (power), 102 GND (power), 108 TDO (out), 109 GND (power), 110 VCC (power), 118 GND (power), 125 VCC (power), 126 GND (power), 127 GND (power), 128 VCC (power), 135 GND (power), 143 VCC (power), 144 GND (power)

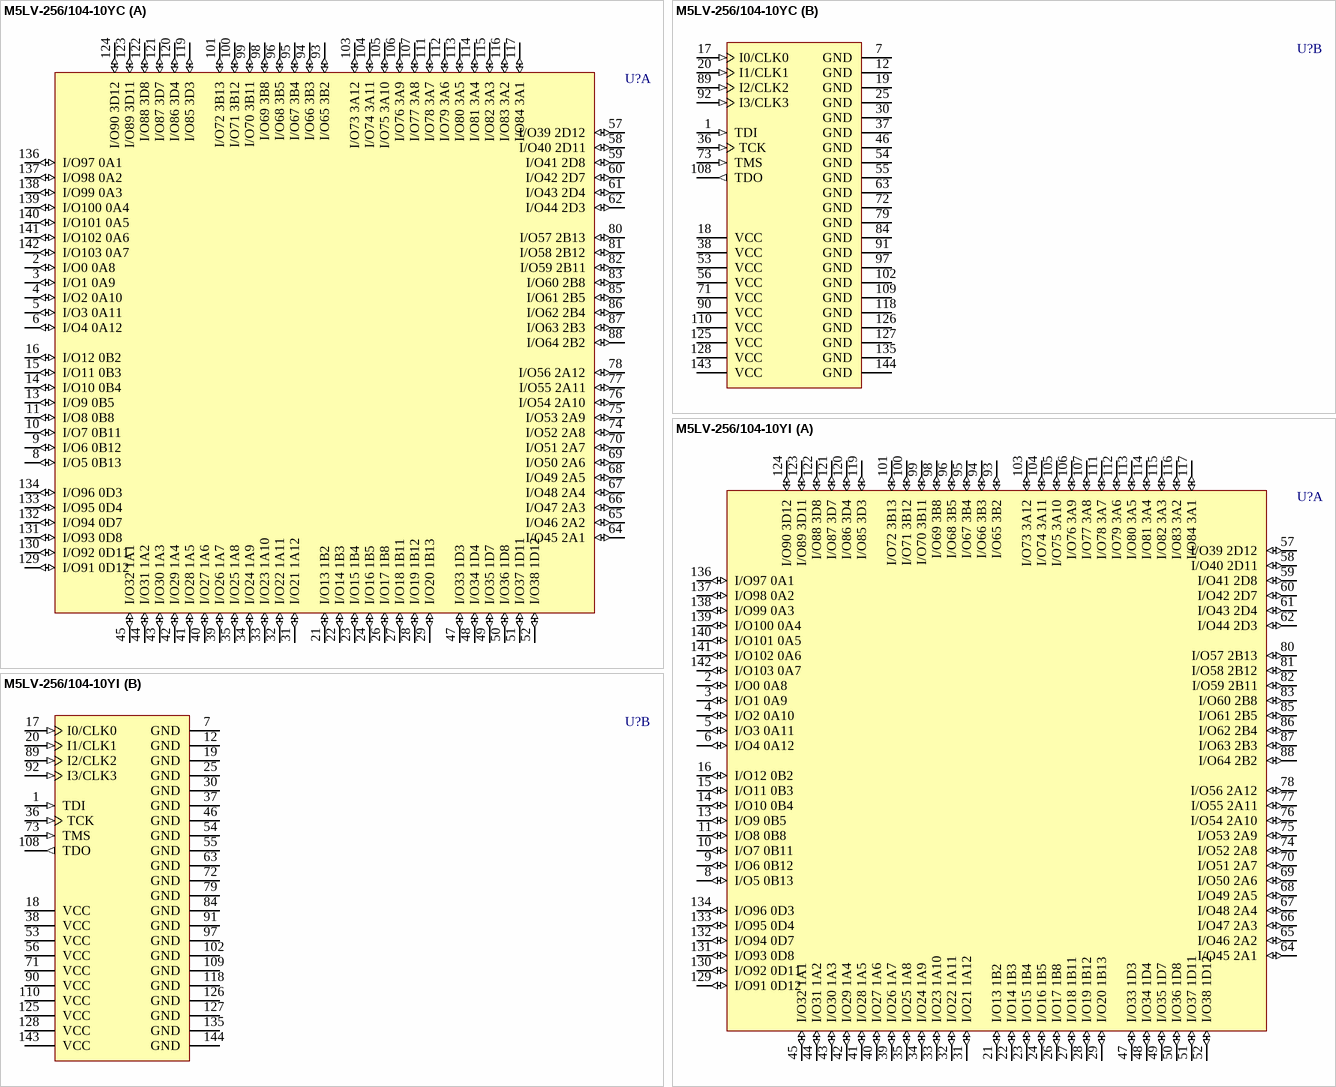
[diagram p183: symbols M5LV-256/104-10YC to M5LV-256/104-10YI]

## M5LV-256/104-10YC
designator U?
High-Density and High-I/O Complex PLD
footprint PQFP144_N (QFP, 144-Leads, Body 28 x 28mm, Pitch 0.65mm, IPC Medium Density)
footprint PQFP144_L (QFP, 144-Leads, Body 28 x 28mm, Pitch 0.65mm, IPC High Density)
footprint PQFP144_M (QFP, 144-Leads, Body 28 x 28mm, Pitch 0.65mm, IPC Low Density)
3D model M5LV-PQFP144 (144-Pin Quad Flat Pack 0.65 mm Pitch)
part A pins: 2 I/O0 0A8 (io), 3 I/O1 0A9 (io), 4 I/O2 0A10 (io), 5 I/O3 0A11 (io), 6 I/O4 0A12 (io), 8 I/O5 0B13 (io), 9 I/O6 0B12 (io), 10 I/O7 0B11 (io), 11 I/O8 0B8 (io), 13 I/O9 0B5 (io), 14 I/O10 0B4 (io), 15 I/O11 0B3 (io), 16 I/O12 0B2 (io), 21 I/O13 1B2 (io), 22 I/O14 1B3 (io), 23 I/O15 1B4 (io), 24 I/O16 1B5 (io), 26 I/O17 1B8 (io), 27 I/O18 1B11 (io), 28 I/O19 1B12 (io), 29 I/O20 1B13 (io), 31 I/O21 1A12 (io), 32 I/O22 1A11 (io), 33 I/O23 1A10 (io), 34 I/O24 1A9 (io), 35 I/O25 1A8 (io), 39 I/O26 1A7 (io), 40 I/O27 1A6 (io), 41 I/O28 1A5 (io), 42 I/O29 1A4 (io), 43 I/O30 1A3 (io), 44 I/O31 1A2 (io), 45 I/O32 1A1 (io), 47 I/O33 1D3 (io), 48 I/O34 1D4 (io), 49 I/O35 1D7 (io), 50 I/O36 1D8 (io), 51 I/O37 1D11 (io), 52 I/O38 1D12 (io), 57 I/O39 2D12 (io), 58 I/O40 2D11 (io), 59 I/O41 2D8 (io), 60 I/O42 2D7 (io), 61 I/O43 2D4 (io), 62 I/O44 2D3 (io), 64 I/O45 2A1 (io), 65 I/O46 2A2 (io), 66 I/O47 2A3 (io), 67 I/O48 2A4 (io), 68 I/O49 2A5 (io), 69 I/O50 2A6 (io), 70 I/O51 2A7 (io), 74 I/O52 2A8 (io), 75 I/O53 2A9 (io), 76 I/O54 2A10 (io), 77 I/O55 2A11 (io), 78 I/O56 2A12 (io), 80 I/O57 2B13 (io), 81 I/O58 2B12 (io), 82 I/O59 2B11 (io), 83 I/O60 2B8 (io), 85 I/O61 2B5 (io), 86 I/O62 2B4 (io), 87 I/O63 2B3 (io), 88 I/O64 2B2 (io), 93 I/O65 3B2 (io), 94 I/O66 3B3 (io), 95 I/O67 3B4 (io), 96 I/O68 3B5 (io), 98 I/O69 3B8 (io), 99 I/O70 3B11 (io), 100 I/O71 3B12 (io), 101 I/O72 3B13 (io), 103 I/O73 3A12 (io), 104 I/O74 3A11 (io), 105 I/O75 3A10 (io), 106 I/O76 3A9 (io), 107 I/O77 3A8 (io), 111 I/O78 3A7 (io), 112 I/O79 3A6 (io), 113 I/O80 3A5 (io), 114 I/O81 3A4 (io), 115 I/O82 3A3 (io), 116 I/O83 3A2 (io), 117 I/O84 3A1 (io), 119 I/O85 3D3 (io), 120 I/O86 3D4 (io), 121 I/O87 3D7 (io), 122 I/O88 3D8 (io), 123 I/O89 3D11 (io), 124 I/O90 3D12 (io), 129 I/O91 0D12 (io), 130 I/O92 0D11 (io), 131 I/O93 0D8 (io), 132 I/O94 0D7 (io), 133 I/O95 0D4 (io), 134 I/O96 0D3 (io), 136 I/O97 0A1 (io), 137 I/O98 0A2 (io), 138 I/O99 0A3 (io), 139 I/O100 0A4 (io), 140 I/O101 0A5 (io), 141 I/O102 0A6 (io), 142 I/O103 0A7 (io)
part B pins: 1 TDI (in), 7 GND (power), 12 GND (power), 17 I0/CLK0 (in), 18 VCC (power), 19 GND (power), 20 I1/CLK1 (in), 25 GND (power), 30 GND (power), 36 TCK (in), 37 GND (power), 38 VCC (power), 46 GND (power), 53 VCC (power), 54 GND (power), 55 GND (power), 56 VCC (power), 63 GND (power), 71 VCC (power), 72 GND (power), 73 TMS (in), 79 GND (power), 84 GND (power), 89 I2/CLK2 (in), 90 VCC (power), 91 GND (power), 92 I3/CLK3 (in), 97 GND (power), 102 GND (power), 108 TDO (out), 109 GND (power), 110 VCC (power), 118 GND (power), 125 VCC (power), 126 GND (power), 127 GND (power), 128 VCC (power), 135 GND (power), 143 VCC (power), 144 GND (power)

## M5LV-256/104-10YI
designator U?
High-Density and High-I/O Complex PLD
footprint PQFP144_N (QFP, 144-Leads, Body 28 x 28mm, Pitch 0.65mm, IPC Medium Density)
footprint PQFP144_L (QFP, 144-Leads, Body 28 x 28mm, Pitch 0.65mm, IPC High Density)
footprint PQFP144_M (QFP, 144-Leads, Body 28 x 28mm, Pitch 0.65mm, IPC Low Density)
3D model M5LV-PQFP144 (144-Pin Quad Flat Pack 0.65 mm Pitch)
part A pins: 2 I/O0 0A8 (io), 3 I/O1 0A9 (io), 4 I/O2 0A10 (io), 5 I/O3 0A11 (io), 6 I/O4 0A12 (io), 8 I/O5 0B13 (io), 9 I/O6 0B12 (io), 10 I/O7 0B11 (io), 11 I/O8 0B8 (io), 13 I/O9 0B5 (io), 14 I/O10 0B4 (io), 15 I/O11 0B3 (io), 16 I/O12 0B2 (io), 21 I/O13 1B2 (io), 22 I/O14 1B3 (io), 23 I/O15 1B4 (io), 24 I/O16 1B5 (io), 26 I/O17 1B8 (io), 27 I/O18 1B11 (io), 28 I/O19 1B12 (io), 29 I/O20 1B13 (io), 31 I/O21 1A12 (io), 32 I/O22 1A11 (io), 33 I/O23 1A10 (io), 34 I/O24 1A9 (io), 35 I/O25 1A8 (io), 39 I/O26 1A7 (io), 40 I/O27 1A6 (io), 41 I/O28 1A5 (io), 42 I/O29 1A4 (io), 43 I/O30 1A3 (io), 44 I/O31 1A2 (io), 45 I/O32 1A1 (io), 47 I/O33 1D3 (io), 48 I/O34 1D4 (io), 49 I/O35 1D7 (io), 50 I/O36 1D8 (io), 51 I/O37 1D11 (io), 52 I/O38 1D12 (io), 57 I/O39 2D12 (io), 58 I/O40 2D11 (io), 59 I/O41 2D8 (io), 60 I/O42 2D7 (io), 61 I/O43 2D4 (io), 62 I/O44 2D3 (io), 64 I/O45 2A1 (io), 65 I/O46 2A2 (io), 66 I/O47 2A3 (io), 67 I/O48 2A4 (io), 68 I/O49 2A5 (io), 69 I/O50 2A6 (io), 70 I/O51 2A7 (io), 74 I/O52 2A8 (io), 75 I/O53 2A9 (io), 76 I/O54 2A10 (io), 77 I/O55 2A11 (io), 78 I/O56 2A12 (io), 80 I/O57 2B13 (io), 81 I/O58 2B12 (io), 82 I/O59 2B11 (io), 83 I/O60 2B8 (io), 85 I/O61 2B5 (io), 86 I/O62 2B4 (io), 87 I/O63 2B3 (io), 88 I/O64 2B2 (io), 93 I/O65 3B2 (io), 94 I/O66 3B3 (io), 95 I/O67 3B4 (io), 96 I/O68 3B5 (io), 98 I/O69 3B8 (io), 99 I/O70 3B11 (io), 100 I/O71 3B12 (io), 101 I/O72 3B13 (io), 103 I/O73 3A12 (io), 104 I/O74 3A11 (io), 105 I/O75 3A10 (io), 106 I/O76 3A9 (io), 107 I/O77 3A8 (io), 111 I/O78 3A7 (io), 112 I/O79 3A6 (io), 113 I/O80 3A5 (io), 114 I/O81 3A4 (io), 115 I/O82 3A3 (io), 116 I/O83 3A2 (io), 117 I/O84 3A1 (io), 119 I/O85 3D3 (io), 120 I/O86 3D4 (io), 121 I/O87 3D7 (io), 122 I/O88 3D8 (io), 123 I/O89 3D11 (io), 124 I/O90 3D12 (io), 129 I/O91 0D12 (io), 130 I/O92 0D11 (io), 131 I/O93 0D8 (io), 132 I/O94 0D7 (io), 133 I/O95 0D4 (io), 134 I/O96 0D3 (io), 136 I/O97 0A1 (io), 137 I/O98 0A2 (io), 138 I/O99 0A3 (io), 139 I/O100 0A4 (io), 140 I/O101 0A5 (io), 141 I/O102 0A6 (io), 142 I/O103 0A7 (io)
part B pins: 1 TDI (in), 7 GND (power), 12 GND (power), 17 I0/CLK0 (in), 18 VCC (power), 19 GND (power), 20 I1/CLK1 (in), 25 GND (power), 30 GND (power), 36 TCK (in), 37 GND (power), 38 VCC (power), 46 GND (power), 53 VCC (power), 54 GND (power), 55 GND (power), 56 VCC (power), 63 GND (power), 71 VCC (power), 72 GND (power), 73 TMS (in), 79 GND (power), 84 GND (power), 89 I2/CLK2 (in), 90 VCC (power), 91 GND (power), 92 I3/CLK3 (in), 97 GND (power), 102 GND (power), 108 TDO (out), 109 GND (power), 110 VCC (power), 118 GND (power), 125 VCC (power), 126 GND (power), 127 GND (power), 128 VCC (power), 135 GND (power), 143 VCC (power), 144 GND (power)

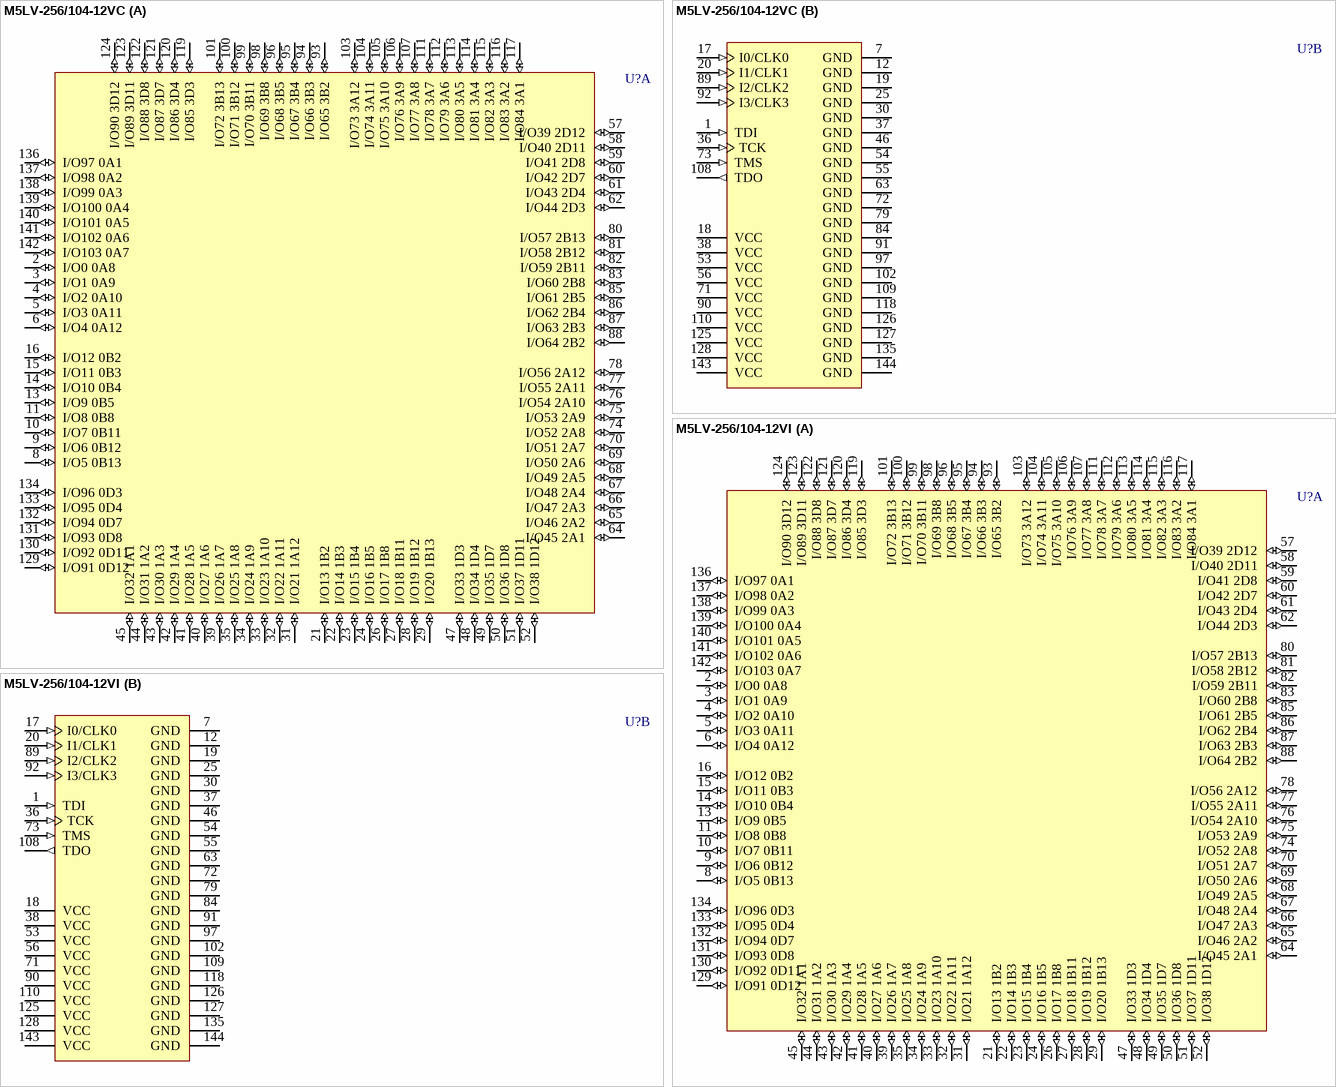
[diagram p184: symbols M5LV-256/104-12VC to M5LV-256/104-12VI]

## M5LV-256/104-12VC
designator U?
High-Density and High-I/O Complex PLD
footprint TQFP144_N (Thin QFP, 144-Leads, Body 20x20mm, Pitch 0.5mm, IPC Medium Density)
footprint TQFP144_L (Thin QFP, 144-Leads, Body 20x20mm, Pitch 0.5mm, IPC High Density)
footprint TQFP144_M (Thin QFP, 144-Leads, Body 20x20mm, Pitch 0.5mm, IPC Low Density)
3D model M5LV-TQFP144 (144-Pin Thin Quad Flat Pack (TQFP144))
part A pins: 2 I/O0 0A8 (io), 3 I/O1 0A9 (io), 4 I/O2 0A10 (io), 5 I/O3 0A11 (io), 6 I/O4 0A12 (io), 8 I/O5 0B13 (io), 9 I/O6 0B12 (io), 10 I/O7 0B11 (io), 11 I/O8 0B8 (io), 13 I/O9 0B5 (io), 14 I/O10 0B4 (io), 15 I/O11 0B3 (io), 16 I/O12 0B2 (io), 21 I/O13 1B2 (io), 22 I/O14 1B3 (io), 23 I/O15 1B4 (io), 24 I/O16 1B5 (io), 26 I/O17 1B8 (io), 27 I/O18 1B11 (io), 28 I/O19 1B12 (io), 29 I/O20 1B13 (io), 31 I/O21 1A12 (io), 32 I/O22 1A11 (io), 33 I/O23 1A10 (io), 34 I/O24 1A9 (io), 35 I/O25 1A8 (io), 39 I/O26 1A7 (io), 40 I/O27 1A6 (io), 41 I/O28 1A5 (io), 42 I/O29 1A4 (io), 43 I/O30 1A3 (io), 44 I/O31 1A2 (io), 45 I/O32 1A1 (io), 47 I/O33 1D3 (io), 48 I/O34 1D4 (io), 49 I/O35 1D7 (io), 50 I/O36 1D8 (io), 51 I/O37 1D11 (io), 52 I/O38 1D12 (io), 57 I/O39 2D12 (io), 58 I/O40 2D11 (io), 59 I/O41 2D8 (io), 60 I/O42 2D7 (io), 61 I/O43 2D4 (io), 62 I/O44 2D3 (io), 64 I/O45 2A1 (io), 65 I/O46 2A2 (io), 66 I/O47 2A3 (io), 67 I/O48 2A4 (io), 68 I/O49 2A5 (io), 69 I/O50 2A6 (io), 70 I/O51 2A7 (io), 74 I/O52 2A8 (io), 75 I/O53 2A9 (io), 76 I/O54 2A10 (io), 77 I/O55 2A11 (io), 78 I/O56 2A12 (io), 80 I/O57 2B13 (io), 81 I/O58 2B12 (io), 82 I/O59 2B11 (io), 83 I/O60 2B8 (io), 85 I/O61 2B5 (io), 86 I/O62 2B4 (io), 87 I/O63 2B3 (io), 88 I/O64 2B2 (io), 93 I/O65 3B2 (io), 94 I/O66 3B3 (io), 95 I/O67 3B4 (io), 96 I/O68 3B5 (io), 98 I/O69 3B8 (io), 99 I/O70 3B11 (io), 100 I/O71 3B12 (io), 101 I/O72 3B13 (io), 103 I/O73 3A12 (io), 104 I/O74 3A11 (io), 105 I/O75 3A10 (io), 106 I/O76 3A9 (io), 107 I/O77 3A8 (io), 111 I/O78 3A7 (io), 112 I/O79 3A6 (io), 113 I/O80 3A5 (io), 114 I/O81 3A4 (io), 115 I/O82 3A3 (io), 116 I/O83 3A2 (io), 117 I/O84 3A1 (io), 119 I/O85 3D3 (io), 120 I/O86 3D4 (io), 121 I/O87 3D7 (io), 122 I/O88 3D8 (io), 123 I/O89 3D11 (io), 124 I/O90 3D12 (io), 129 I/O91 0D12 (io), 130 I/O92 0D11 (io), 131 I/O93 0D8 (io), 132 I/O94 0D7 (io), 133 I/O95 0D4 (io), 134 I/O96 0D3 (io), 136 I/O97 0A1 (io), 137 I/O98 0A2 (io), 138 I/O99 0A3 (io), 139 I/O100 0A4 (io), 140 I/O101 0A5 (io), 141 I/O102 0A6 (io), 142 I/O103 0A7 (io)
part B pins: 1 TDI (in), 7 GND (power), 12 GND (power), 17 I0/CLK0 (in), 18 VCC (power), 19 GND (power), 20 I1/CLK1 (in), 25 GND (power), 30 GND (power), 36 TCK (in), 37 GND (power), 38 VCC (power), 46 GND (power), 53 VCC (power), 54 GND (power), 55 GND (power), 56 VCC (power), 63 GND (power), 71 VCC (power), 72 GND (power), 73 TMS (in), 79 GND (power), 84 GND (power), 89 I2/CLK2 (in), 90 VCC (power), 91 GND (power), 92 I3/CLK3 (in), 97 GND (power), 102 GND (power), 108 TDO (out), 109 GND (power), 110 VCC (power), 118 GND (power), 125 VCC (power), 126 GND (power), 127 GND (power), 128 VCC (power), 135 GND (power), 143 VCC (power), 144 GND (power)

## M5LV-256/104-12VI
designator U?
High-Density and High-I/O Complex PLD
footprint TQFP144_N (Thin QFP, 144-Leads, Body 20x20mm, Pitch 0.5mm, IPC Medium Density)
footprint TQFP144_L (Thin QFP, 144-Leads, Body 20x20mm, Pitch 0.5mm, IPC High Density)
footprint TQFP144_M (Thin QFP, 144-Leads, Body 20x20mm, Pitch 0.5mm, IPC Low Density)
3D model M5LV-TQFP144 (144-Pin Thin Quad Flat Pack (TQFP144))
part A pins: 2 I/O0 0A8 (io), 3 I/O1 0A9 (io), 4 I/O2 0A10 (io), 5 I/O3 0A11 (io), 6 I/O4 0A12 (io), 8 I/O5 0B13 (io), 9 I/O6 0B12 (io), 10 I/O7 0B11 (io), 11 I/O8 0B8 (io), 13 I/O9 0B5 (io), 14 I/O10 0B4 (io), 15 I/O11 0B3 (io), 16 I/O12 0B2 (io), 21 I/O13 1B2 (io), 22 I/O14 1B3 (io), 23 I/O15 1B4 (io), 24 I/O16 1B5 (io), 26 I/O17 1B8 (io), 27 I/O18 1B11 (io), 28 I/O19 1B12 (io), 29 I/O20 1B13 (io), 31 I/O21 1A12 (io), 32 I/O22 1A11 (io), 33 I/O23 1A10 (io), 34 I/O24 1A9 (io), 35 I/O25 1A8 (io), 39 I/O26 1A7 (io), 40 I/O27 1A6 (io), 41 I/O28 1A5 (io), 42 I/O29 1A4 (io), 43 I/O30 1A3 (io), 44 I/O31 1A2 (io), 45 I/O32 1A1 (io), 47 I/O33 1D3 (io), 48 I/O34 1D4 (io), 49 I/O35 1D7 (io), 50 I/O36 1D8 (io), 51 I/O37 1D11 (io), 52 I/O38 1D12 (io), 57 I/O39 2D12 (io), 58 I/O40 2D11 (io), 59 I/O41 2D8 (io), 60 I/O42 2D7 (io), 61 I/O43 2D4 (io), 62 I/O44 2D3 (io), 64 I/O45 2A1 (io), 65 I/O46 2A2 (io), 66 I/O47 2A3 (io), 67 I/O48 2A4 (io), 68 I/O49 2A5 (io), 69 I/O50 2A6 (io), 70 I/O51 2A7 (io), 74 I/O52 2A8 (io), 75 I/O53 2A9 (io), 76 I/O54 2A10 (io), 77 I/O55 2A11 (io), 78 I/O56 2A12 (io), 80 I/O57 2B13 (io), 81 I/O58 2B12 (io), 82 I/O59 2B11 (io), 83 I/O60 2B8 (io), 85 I/O61 2B5 (io), 86 I/O62 2B4 (io), 87 I/O63 2B3 (io), 88 I/O64 2B2 (io), 93 I/O65 3B2 (io), 94 I/O66 3B3 (io), 95 I/O67 3B4 (io), 96 I/O68 3B5 (io), 98 I/O69 3B8 (io), 99 I/O70 3B11 (io), 100 I/O71 3B12 (io), 101 I/O72 3B13 (io), 103 I/O73 3A12 (io), 104 I/O74 3A11 (io), 105 I/O75 3A10 (io), 106 I/O76 3A9 (io), 107 I/O77 3A8 (io), 111 I/O78 3A7 (io), 112 I/O79 3A6 (io), 113 I/O80 3A5 (io), 114 I/O81 3A4 (io), 115 I/O82 3A3 (io), 116 I/O83 3A2 (io), 117 I/O84 3A1 (io), 119 I/O85 3D3 (io), 120 I/O86 3D4 (io), 121 I/O87 3D7 (io), 122 I/O88 3D8 (io), 123 I/O89 3D11 (io), 124 I/O90 3D12 (io), 129 I/O91 0D12 (io), 130 I/O92 0D11 (io), 131 I/O93 0D8 (io), 132 I/O94 0D7 (io), 133 I/O95 0D4 (io), 134 I/O96 0D3 (io), 136 I/O97 0A1 (io), 137 I/O98 0A2 (io), 138 I/O99 0A3 (io), 139 I/O100 0A4 (io), 140 I/O101 0A5 (io), 141 I/O102 0A6 (io), 142 I/O103 0A7 (io)
part B pins: 1 TDI (in), 7 GND (power), 12 GND (power), 17 I0/CLK0 (in), 18 VCC (power), 19 GND (power), 20 I1/CLK1 (in), 25 GND (power), 30 GND (power), 36 TCK (in), 37 GND (power), 38 VCC (power), 46 GND (power), 53 VCC (power), 54 GND (power), 55 GND (power), 56 VCC (power), 63 GND (power), 71 VCC (power), 72 GND (power), 73 TMS (in), 79 GND (power), 84 GND (power), 89 I2/CLK2 (in), 90 VCC (power), 91 GND (power), 92 I3/CLK3 (in), 97 GND (power), 102 GND (power), 108 TDO (out), 109 GND (power), 110 VCC (power), 118 GND (power), 125 VCC (power), 126 GND (power), 127 GND (power), 128 VCC (power), 135 GND (power), 143 VCC (power), 144 GND (power)

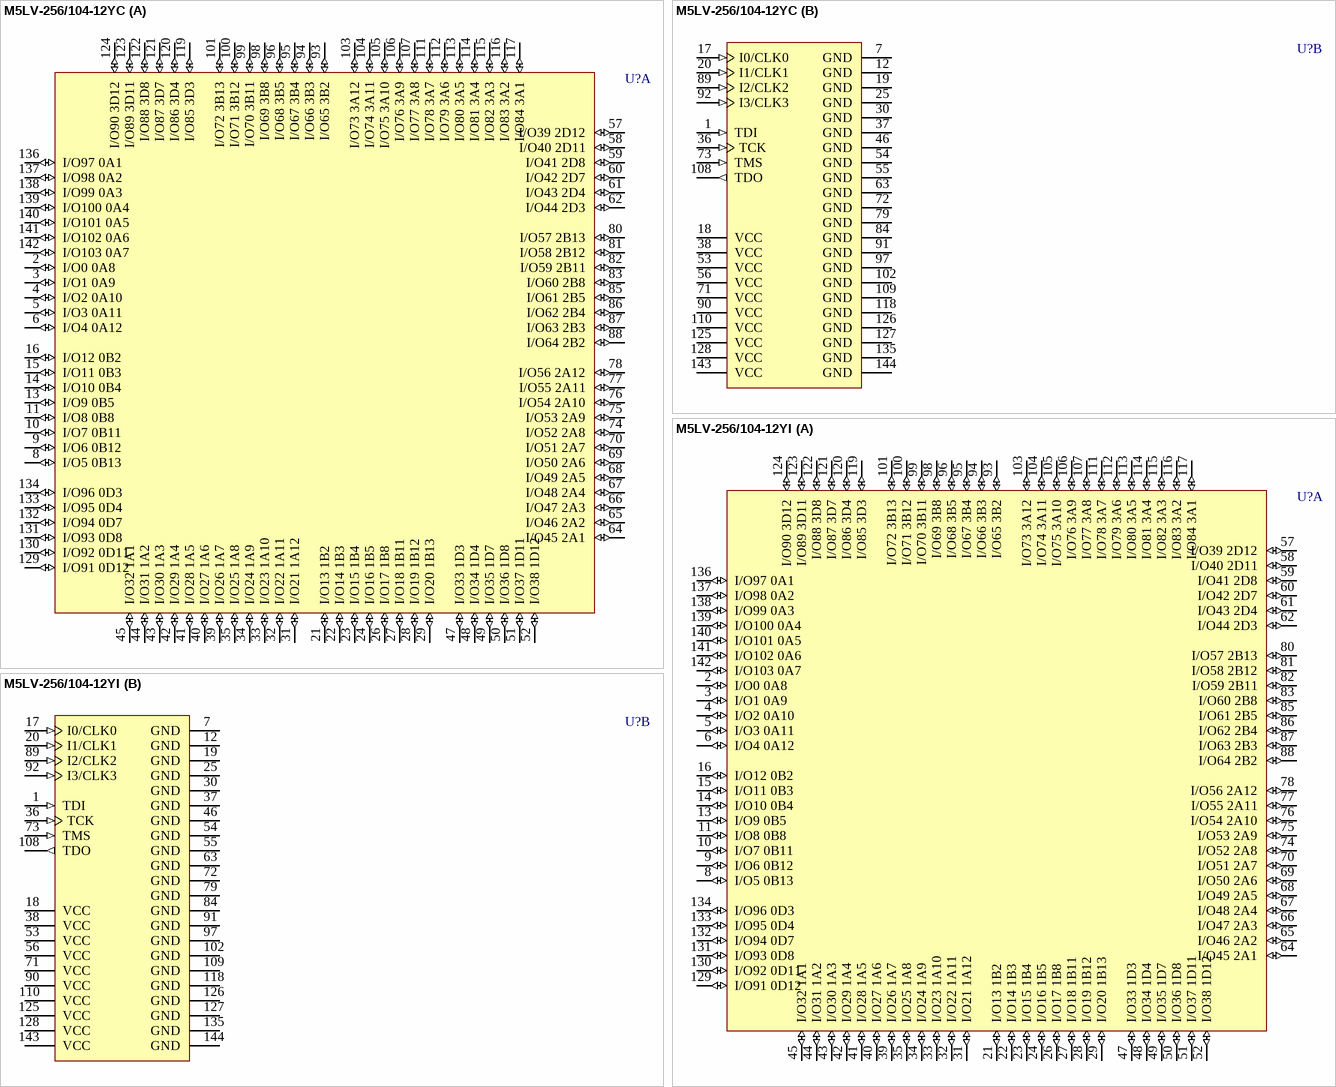
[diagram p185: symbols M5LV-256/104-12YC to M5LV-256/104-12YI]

## M5LV-256/104-12YC
designator U?
High-Density and High-I/O Complex PLD
footprint PQFP144_N (QFP, 144-Leads, Body 28 x 28mm, Pitch 0.65mm, IPC Medium Density)
footprint PQFP144_L (QFP, 144-Leads, Body 28 x 28mm, Pitch 0.65mm, IPC High Density)
footprint PQFP144_M (QFP, 144-Leads, Body 28 x 28mm, Pitch 0.65mm, IPC Low Density)
3D model M5LV-PQFP144 (144-Pin Quad Flat Pack 0.65 mm Pitch)
part A pins: 2 I/O0 0A8 (io), 3 I/O1 0A9 (io), 4 I/O2 0A10 (io), 5 I/O3 0A11 (io), 6 I/O4 0A12 (io), 8 I/O5 0B13 (io), 9 I/O6 0B12 (io), 10 I/O7 0B11 (io), 11 I/O8 0B8 (io), 13 I/O9 0B5 (io), 14 I/O10 0B4 (io), 15 I/O11 0B3 (io), 16 I/O12 0B2 (io), 21 I/O13 1B2 (io), 22 I/O14 1B3 (io), 23 I/O15 1B4 (io), 24 I/O16 1B5 (io), 26 I/O17 1B8 (io), 27 I/O18 1B11 (io), 28 I/O19 1B12 (io), 29 I/O20 1B13 (io), 31 I/O21 1A12 (io), 32 I/O22 1A11 (io), 33 I/O23 1A10 (io), 34 I/O24 1A9 (io), 35 I/O25 1A8 (io), 39 I/O26 1A7 (io), 40 I/O27 1A6 (io), 41 I/O28 1A5 (io), 42 I/O29 1A4 (io), 43 I/O30 1A3 (io), 44 I/O31 1A2 (io), 45 I/O32 1A1 (io), 47 I/O33 1D3 (io), 48 I/O34 1D4 (io), 49 I/O35 1D7 (io), 50 I/O36 1D8 (io), 51 I/O37 1D11 (io), 52 I/O38 1D12 (io), 57 I/O39 2D12 (io), 58 I/O40 2D11 (io), 59 I/O41 2D8 (io), 60 I/O42 2D7 (io), 61 I/O43 2D4 (io), 62 I/O44 2D3 (io), 64 I/O45 2A1 (io), 65 I/O46 2A2 (io), 66 I/O47 2A3 (io), 67 I/O48 2A4 (io), 68 I/O49 2A5 (io), 69 I/O50 2A6 (io), 70 I/O51 2A7 (io), 74 I/O52 2A8 (io), 75 I/O53 2A9 (io), 76 I/O54 2A10 (io), 77 I/O55 2A11 (io), 78 I/O56 2A12 (io), 80 I/O57 2B13 (io), 81 I/O58 2B12 (io), 82 I/O59 2B11 (io), 83 I/O60 2B8 (io), 85 I/O61 2B5 (io), 86 I/O62 2B4 (io), 87 I/O63 2B3 (io), 88 I/O64 2B2 (io), 93 I/O65 3B2 (io), 94 I/O66 3B3 (io), 95 I/O67 3B4 (io), 96 I/O68 3B5 (io), 98 I/O69 3B8 (io), 99 I/O70 3B11 (io), 100 I/O71 3B12 (io), 101 I/O72 3B13 (io), 103 I/O73 3A12 (io), 104 I/O74 3A11 (io), 105 I/O75 3A10 (io), 106 I/O76 3A9 (io), 107 I/O77 3A8 (io), 111 I/O78 3A7 (io), 112 I/O79 3A6 (io), 113 I/O80 3A5 (io), 114 I/O81 3A4 (io), 115 I/O82 3A3 (io), 116 I/O83 3A2 (io), 117 I/O84 3A1 (io), 119 I/O85 3D3 (io), 120 I/O86 3D4 (io), 121 I/O87 3D7 (io), 122 I/O88 3D8 (io), 123 I/O89 3D11 (io), 124 I/O90 3D12 (io), 129 I/O91 0D12 (io), 130 I/O92 0D11 (io), 131 I/O93 0D8 (io), 132 I/O94 0D7 (io), 133 I/O95 0D4 (io), 134 I/O96 0D3 (io), 136 I/O97 0A1 (io), 137 I/O98 0A2 (io), 138 I/O99 0A3 (io), 139 I/O100 0A4 (io), 140 I/O101 0A5 (io), 141 I/O102 0A6 (io), 142 I/O103 0A7 (io)
part B pins: 1 TDI (in), 7 GND (power), 12 GND (power), 17 I0/CLK0 (in), 18 VCC (power), 19 GND (power), 20 I1/CLK1 (in), 25 GND (power), 30 GND (power), 36 TCK (in), 37 GND (power), 38 VCC (power), 46 GND (power), 53 VCC (power), 54 GND (power), 55 GND (power), 56 VCC (power), 63 GND (power), 71 VCC (power), 72 GND (power), 73 TMS (in), 79 GND (power), 84 GND (power), 89 I2/CLK2 (in), 90 VCC (power), 91 GND (power), 92 I3/CLK3 (in), 97 GND (power), 102 GND (power), 108 TDO (out), 109 GND (power), 110 VCC (power), 118 GND (power), 125 VCC (power), 126 GND (power), 127 GND (power), 128 VCC (power), 135 GND (power), 143 VCC (power), 144 GND (power)

## M5LV-256/104-12YI
designator U?
High-Density and High-I/O Complex PLD
footprint PQFP144_N (QFP, 144-Leads, Body 28 x 28mm, Pitch 0.65mm, IPC Medium Density)
footprint PQFP144_L (QFP, 144-Leads, Body 28 x 28mm, Pitch 0.65mm, IPC High Density)
footprint PQFP144_M (QFP, 144-Leads, Body 28 x 28mm, Pitch 0.65mm, IPC Low Density)
3D model M5LV-PQFP144 (144-Pin Quad Flat Pack 0.65 mm Pitch)
part A pins: 2 I/O0 0A8 (io), 3 I/O1 0A9 (io), 4 I/O2 0A10 (io), 5 I/O3 0A11 (io), 6 I/O4 0A12 (io), 8 I/O5 0B13 (io), 9 I/O6 0B12 (io), 10 I/O7 0B11 (io), 11 I/O8 0B8 (io), 13 I/O9 0B5 (io), 14 I/O10 0B4 (io), 15 I/O11 0B3 (io), 16 I/O12 0B2 (io), 21 I/O13 1B2 (io), 22 I/O14 1B3 (io), 23 I/O15 1B4 (io), 24 I/O16 1B5 (io), 26 I/O17 1B8 (io), 27 I/O18 1B11 (io), 28 I/O19 1B12 (io), 29 I/O20 1B13 (io), 31 I/O21 1A12 (io), 32 I/O22 1A11 (io), 33 I/O23 1A10 (io), 34 I/O24 1A9 (io), 35 I/O25 1A8 (io), 39 I/O26 1A7 (io), 40 I/O27 1A6 (io), 41 I/O28 1A5 (io), 42 I/O29 1A4 (io), 43 I/O30 1A3 (io), 44 I/O31 1A2 (io), 45 I/O32 1A1 (io), 47 I/O33 1D3 (io), 48 I/O34 1D4 (io), 49 I/O35 1D7 (io), 50 I/O36 1D8 (io), 51 I/O37 1D11 (io), 52 I/O38 1D12 (io), 57 I/O39 2D12 (io), 58 I/O40 2D11 (io), 59 I/O41 2D8 (io), 60 I/O42 2D7 (io), 61 I/O43 2D4 (io), 62 I/O44 2D3 (io), 64 I/O45 2A1 (io), 65 I/O46 2A2 (io), 66 I/O47 2A3 (io), 67 I/O48 2A4 (io), 68 I/O49 2A5 (io), 69 I/O50 2A6 (io), 70 I/O51 2A7 (io), 74 I/O52 2A8 (io), 75 I/O53 2A9 (io), 76 I/O54 2A10 (io), 77 I/O55 2A11 (io), 78 I/O56 2A12 (io), 80 I/O57 2B13 (io), 81 I/O58 2B12 (io), 82 I/O59 2B11 (io), 83 I/O60 2B8 (io), 85 I/O61 2B5 (io), 86 I/O62 2B4 (io), 87 I/O63 2B3 (io), 88 I/O64 2B2 (io), 93 I/O65 3B2 (io), 94 I/O66 3B3 (io), 95 I/O67 3B4 (io), 96 I/O68 3B5 (io), 98 I/O69 3B8 (io), 99 I/O70 3B11 (io), 100 I/O71 3B12 (io), 101 I/O72 3B13 (io), 103 I/O73 3A12 (io), 104 I/O74 3A11 (io), 105 I/O75 3A10 (io), 106 I/O76 3A9 (io), 107 I/O77 3A8 (io), 111 I/O78 3A7 (io), 112 I/O79 3A6 (io), 113 I/O80 3A5 (io), 114 I/O81 3A4 (io), 115 I/O82 3A3 (io), 116 I/O83 3A2 (io), 117 I/O84 3A1 (io), 119 I/O85 3D3 (io), 120 I/O86 3D4 (io), 121 I/O87 3D7 (io), 122 I/O88 3D8 (io), 123 I/O89 3D11 (io), 124 I/O90 3D12 (io), 129 I/O91 0D12 (io), 130 I/O92 0D11 (io), 131 I/O93 0D8 (io), 132 I/O94 0D7 (io), 133 I/O95 0D4 (io), 134 I/O96 0D3 (io), 136 I/O97 0A1 (io), 137 I/O98 0A2 (io), 138 I/O99 0A3 (io), 139 I/O100 0A4 (io), 140 I/O101 0A5 (io), 141 I/O102 0A6 (io), 142 I/O103 0A7 (io)
part B pins: 1 TDI (in), 7 GND (power), 12 GND (power), 17 I0/CLK0 (in), 18 VCC (power), 19 GND (power), 20 I1/CLK1 (in), 25 GND (power), 30 GND (power), 36 TCK (in), 37 GND (power), 38 VCC (power), 46 GND (power), 53 VCC (power), 54 GND (power), 55 GND (power), 56 VCC (power), 63 GND (power), 71 VCC (power), 72 GND (power), 73 TMS (in), 79 GND (power), 84 GND (power), 89 I2/CLK2 (in), 90 VCC (power), 91 GND (power), 92 I3/CLK3 (in), 97 GND (power), 102 GND (power), 108 TDO (out), 109 GND (power), 110 VCC (power), 118 GND (power), 125 VCC (power), 126 GND (power), 127 GND (power), 128 VCC (power), 135 GND (power), 143 VCC (power), 144 GND (power)

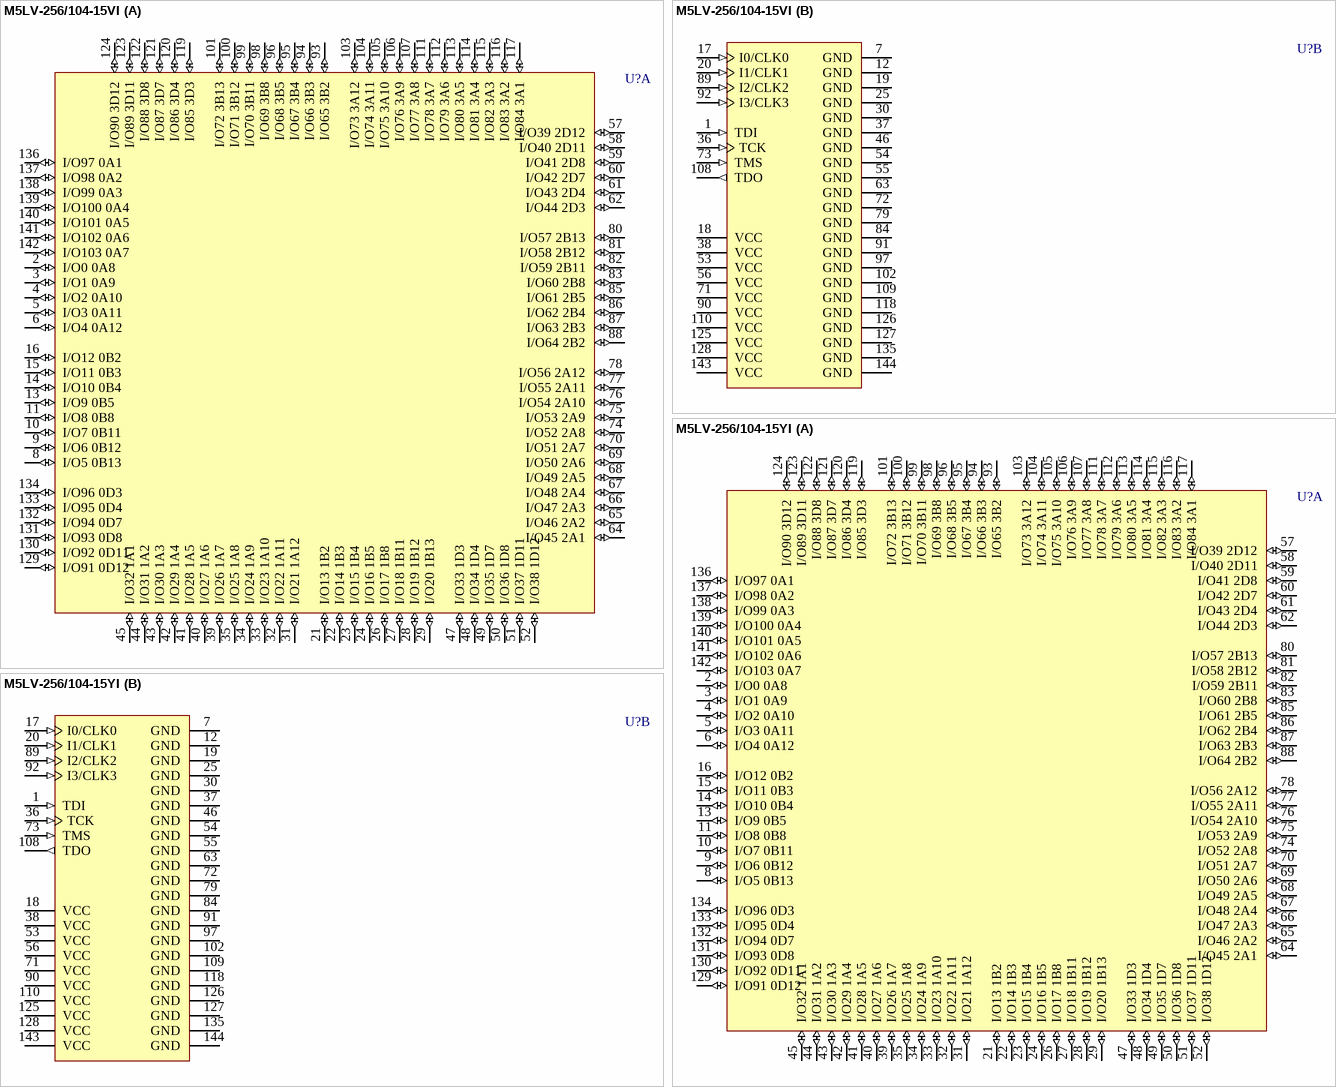
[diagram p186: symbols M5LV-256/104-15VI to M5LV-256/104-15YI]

## M5LV-256/104-15VI
designator U?
High-Density and High-I/O Complex PLD
footprint TQFP144_N (Thin QFP, 144-Leads, Body 20x20mm, Pitch 0.5mm, IPC Medium Density)
footprint TQFP144_L (Thin QFP, 144-Leads, Body 20x20mm, Pitch 0.5mm, IPC High Density)
footprint TQFP144_M (Thin QFP, 144-Leads, Body 20x20mm, Pitch 0.5mm, IPC Low Density)
3D model M5LV-TQFP144 (144-Pin Thin Quad Flat Pack (TQFP144))
part A pins: 2 I/O0 0A8 (io), 3 I/O1 0A9 (io), 4 I/O2 0A10 (io), 5 I/O3 0A11 (io), 6 I/O4 0A12 (io), 8 I/O5 0B13 (io), 9 I/O6 0B12 (io), 10 I/O7 0B11 (io), 11 I/O8 0B8 (io), 13 I/O9 0B5 (io), 14 I/O10 0B4 (io), 15 I/O11 0B3 (io), 16 I/O12 0B2 (io), 21 I/O13 1B2 (io), 22 I/O14 1B3 (io), 23 I/O15 1B4 (io), 24 I/O16 1B5 (io), 26 I/O17 1B8 (io), 27 I/O18 1B11 (io), 28 I/O19 1B12 (io), 29 I/O20 1B13 (io), 31 I/O21 1A12 (io), 32 I/O22 1A11 (io), 33 I/O23 1A10 (io), 34 I/O24 1A9 (io), 35 I/O25 1A8 (io), 39 I/O26 1A7 (io), 40 I/O27 1A6 (io), 41 I/O28 1A5 (io), 42 I/O29 1A4 (io), 43 I/O30 1A3 (io), 44 I/O31 1A2 (io), 45 I/O32 1A1 (io), 47 I/O33 1D3 (io), 48 I/O34 1D4 (io), 49 I/O35 1D7 (io), 50 I/O36 1D8 (io), 51 I/O37 1D11 (io), 52 I/O38 1D12 (io), 57 I/O39 2D12 (io), 58 I/O40 2D11 (io), 59 I/O41 2D8 (io), 60 I/O42 2D7 (io), 61 I/O43 2D4 (io), 62 I/O44 2D3 (io), 64 I/O45 2A1 (io), 65 I/O46 2A2 (io), 66 I/O47 2A3 (io), 67 I/O48 2A4 (io), 68 I/O49 2A5 (io), 69 I/O50 2A6 (io), 70 I/O51 2A7 (io), 74 I/O52 2A8 (io), 75 I/O53 2A9 (io), 76 I/O54 2A10 (io), 77 I/O55 2A11 (io), 78 I/O56 2A12 (io), 80 I/O57 2B13 (io), 81 I/O58 2B12 (io), 82 I/O59 2B11 (io), 83 I/O60 2B8 (io), 85 I/O61 2B5 (io), 86 I/O62 2B4 (io), 87 I/O63 2B3 (io), 88 I/O64 2B2 (io), 93 I/O65 3B2 (io), 94 I/O66 3B3 (io), 95 I/O67 3B4 (io), 96 I/O68 3B5 (io), 98 I/O69 3B8 (io), 99 I/O70 3B11 (io), 100 I/O71 3B12 (io), 101 I/O72 3B13 (io), 103 I/O73 3A12 (io), 104 I/O74 3A11 (io), 105 I/O75 3A10 (io), 106 I/O76 3A9 (io), 107 I/O77 3A8 (io), 111 I/O78 3A7 (io), 112 I/O79 3A6 (io), 113 I/O80 3A5 (io), 114 I/O81 3A4 (io), 115 I/O82 3A3 (io), 116 I/O83 3A2 (io), 117 I/O84 3A1 (io), 119 I/O85 3D3 (io), 120 I/O86 3D4 (io), 121 I/O87 3D7 (io), 122 I/O88 3D8 (io), 123 I/O89 3D11 (io), 124 I/O90 3D12 (io), 129 I/O91 0D12 (io), 130 I/O92 0D11 (io), 131 I/O93 0D8 (io), 132 I/O94 0D7 (io), 133 I/O95 0D4 (io), 134 I/O96 0D3 (io), 136 I/O97 0A1 (io), 137 I/O98 0A2 (io), 138 I/O99 0A3 (io), 139 I/O100 0A4 (io), 140 I/O101 0A5 (io), 141 I/O102 0A6 (io), 142 I/O103 0A7 (io)
part B pins: 1 TDI (in), 7 GND (power), 12 GND (power), 17 I0/CLK0 (in), 18 VCC (power), 19 GND (power), 20 I1/CLK1 (in), 25 GND (power), 30 GND (power), 36 TCK (in), 37 GND (power), 38 VCC (power), 46 GND (power), 53 VCC (power), 54 GND (power), 55 GND (power), 56 VCC (power), 63 GND (power), 71 VCC (power), 72 GND (power), 73 TMS (in), 79 GND (power), 84 GND (power), 89 I2/CLK2 (in), 90 VCC (power), 91 GND (power), 92 I3/CLK3 (in), 97 GND (power), 102 GND (power), 108 TDO (out), 109 GND (power), 110 VCC (power), 118 GND (power), 125 VCC (power), 126 GND (power), 127 GND (power), 128 VCC (power), 135 GND (power), 143 VCC (power), 144 GND (power)

## M5LV-256/104-15YI
designator U?
High-Density and High-I/O Complex PLD
footprint PQFP144_N (QFP, 144-Leads, Body 28 x 28mm, Pitch 0.65mm, IPC Medium Density)
footprint PQFP144_L (QFP, 144-Leads, Body 28 x 28mm, Pitch 0.65mm, IPC High Density)
footprint PQFP144_M (QFP, 144-Leads, Body 28 x 28mm, Pitch 0.65mm, IPC Low Density)
3D model M5LV-PQFP144 (144-Pin Quad Flat Pack 0.65 mm Pitch)
part A pins: 2 I/O0 0A8 (io), 3 I/O1 0A9 (io), 4 I/O2 0A10 (io), 5 I/O3 0A11 (io), 6 I/O4 0A12 (io), 8 I/O5 0B13 (io), 9 I/O6 0B12 (io), 10 I/O7 0B11 (io), 11 I/O8 0B8 (io), 13 I/O9 0B5 (io), 14 I/O10 0B4 (io), 15 I/O11 0B3 (io), 16 I/O12 0B2 (io), 21 I/O13 1B2 (io), 22 I/O14 1B3 (io), 23 I/O15 1B4 (io), 24 I/O16 1B5 (io), 26 I/O17 1B8 (io), 27 I/O18 1B11 (io), 28 I/O19 1B12 (io), 29 I/O20 1B13 (io), 31 I/O21 1A12 (io), 32 I/O22 1A11 (io), 33 I/O23 1A10 (io), 34 I/O24 1A9 (io), 35 I/O25 1A8 (io), 39 I/O26 1A7 (io), 40 I/O27 1A6 (io), 41 I/O28 1A5 (io), 42 I/O29 1A4 (io), 43 I/O30 1A3 (io), 44 I/O31 1A2 (io), 45 I/O32 1A1 (io), 47 I/O33 1D3 (io), 48 I/O34 1D4 (io), 49 I/O35 1D7 (io), 50 I/O36 1D8 (io), 51 I/O37 1D11 (io), 52 I/O38 1D12 (io), 57 I/O39 2D12 (io), 58 I/O40 2D11 (io), 59 I/O41 2D8 (io), 60 I/O42 2D7 (io), 61 I/O43 2D4 (io), 62 I/O44 2D3 (io), 64 I/O45 2A1 (io), 65 I/O46 2A2 (io), 66 I/O47 2A3 (io), 67 I/O48 2A4 (io), 68 I/O49 2A5 (io), 69 I/O50 2A6 (io), 70 I/O51 2A7 (io), 74 I/O52 2A8 (io), 75 I/O53 2A9 (io), 76 I/O54 2A10 (io), 77 I/O55 2A11 (io), 78 I/O56 2A12 (io), 80 I/O57 2B13 (io), 81 I/O58 2B12 (io), 82 I/O59 2B11 (io), 83 I/O60 2B8 (io), 85 I/O61 2B5 (io), 86 I/O62 2B4 (io), 87 I/O63 2B3 (io), 88 I/O64 2B2 (io), 93 I/O65 3B2 (io), 94 I/O66 3B3 (io), 95 I/O67 3B4 (io), 96 I/O68 3B5 (io), 98 I/O69 3B8 (io), 99 I/O70 3B11 (io), 100 I/O71 3B12 (io), 101 I/O72 3B13 (io), 103 I/O73 3A12 (io), 104 I/O74 3A11 (io), 105 I/O75 3A10 (io), 106 I/O76 3A9 (io), 107 I/O77 3A8 (io), 111 I/O78 3A7 (io), 112 I/O79 3A6 (io), 113 I/O80 3A5 (io), 114 I/O81 3A4 (io), 115 I/O82 3A3 (io), 116 I/O83 3A2 (io), 117 I/O84 3A1 (io), 119 I/O85 3D3 (io), 120 I/O86 3D4 (io), 121 I/O87 3D7 (io), 122 I/O88 3D8 (io), 123 I/O89 3D11 (io), 124 I/O90 3D12 (io), 129 I/O91 0D12 (io), 130 I/O92 0D11 (io), 131 I/O93 0D8 (io), 132 I/O94 0D7 (io), 133 I/O95 0D4 (io), 134 I/O96 0D3 (io), 136 I/O97 0A1 (io), 137 I/O98 0A2 (io), 138 I/O99 0A3 (io), 139 I/O100 0A4 (io), 140 I/O101 0A5 (io), 141 I/O102 0A6 (io), 142 I/O103 0A7 (io)
part B pins: 1 TDI (in), 7 GND (power), 12 GND (power), 17 I0/CLK0 (in), 18 VCC (power), 19 GND (power), 20 I1/CLK1 (in), 25 GND (power), 30 GND (power), 36 TCK (in), 37 GND (power), 38 VCC (power), 46 GND (power), 53 VCC (power), 54 GND (power), 55 GND (power), 56 VCC (power), 63 GND (power), 71 VCC (power), 72 GND (power), 73 TMS (in), 79 GND (power), 84 GND (power), 89 I2/CLK2 (in), 90 VCC (power), 91 GND (power), 92 I3/CLK3 (in), 97 GND (power), 102 GND (power), 108 TDO (out), 109 GND (power), 110 VCC (power), 118 GND (power), 125 VCC (power), 126 GND (power), 127 GND (power), 128 VCC (power), 135 GND (power), 143 VCC (power), 144 GND (power)

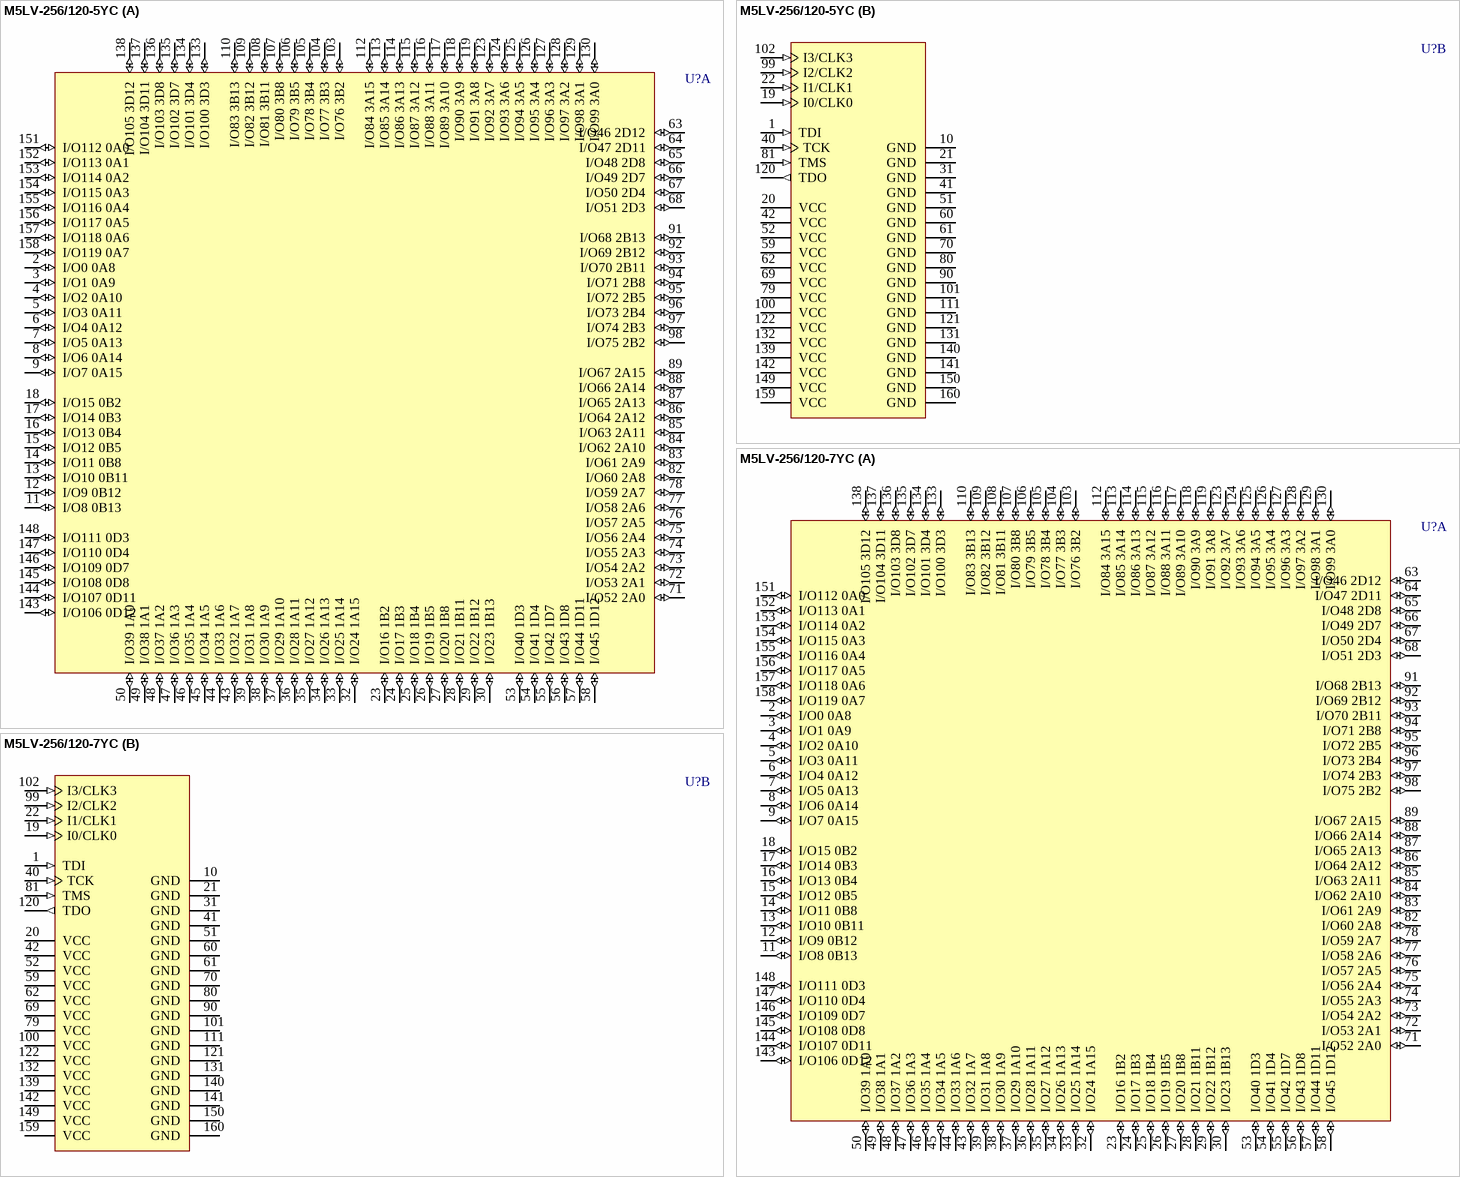
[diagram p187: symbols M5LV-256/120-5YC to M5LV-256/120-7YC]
